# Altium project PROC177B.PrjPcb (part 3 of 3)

## Sheet PROC177B_CAN_LIN_PHY_Interface.SchDoc: CAN_LIN_PHY_INTERFACE
size 431 x 279 mm; Date: Not shown in title block; ApprovedBy: Not shown in title block; CheckedBy: Not shown in title block; Author: Not shown in title block; CompanyName: Not shown in title block; DrawnBy: Mistral; Engineer: Not shown in title block; Organization: Not shown in title block; Address1: Not shown in title block; Address2: Not shown in title block; Address3: Not shown in title block; Address4: Not shown in title block; DocumentNumber: 13; Revision: Use project parameter SCH_Rev; SheetNumber: 13; SheetTotal: 17; PageSetup: Record=PageOptions¦CenterHorizontal=True¦CenterVertical=True¦PrintScale=1.00¦XCorrection=1.00¦YCorrection=1.00¦PrintKind=0¦BorderSize=5000000¦LeftOffset=0¦BottomOffset=0¦Orientation=2¦PaperLength=1000¦PaperWidth=1000¦Scale=100¦PaperSource=15¦PrintQuality=600¦MediaType=1¦DitherType=10¦PaperKind=Letter¦PrintScaleMode=1
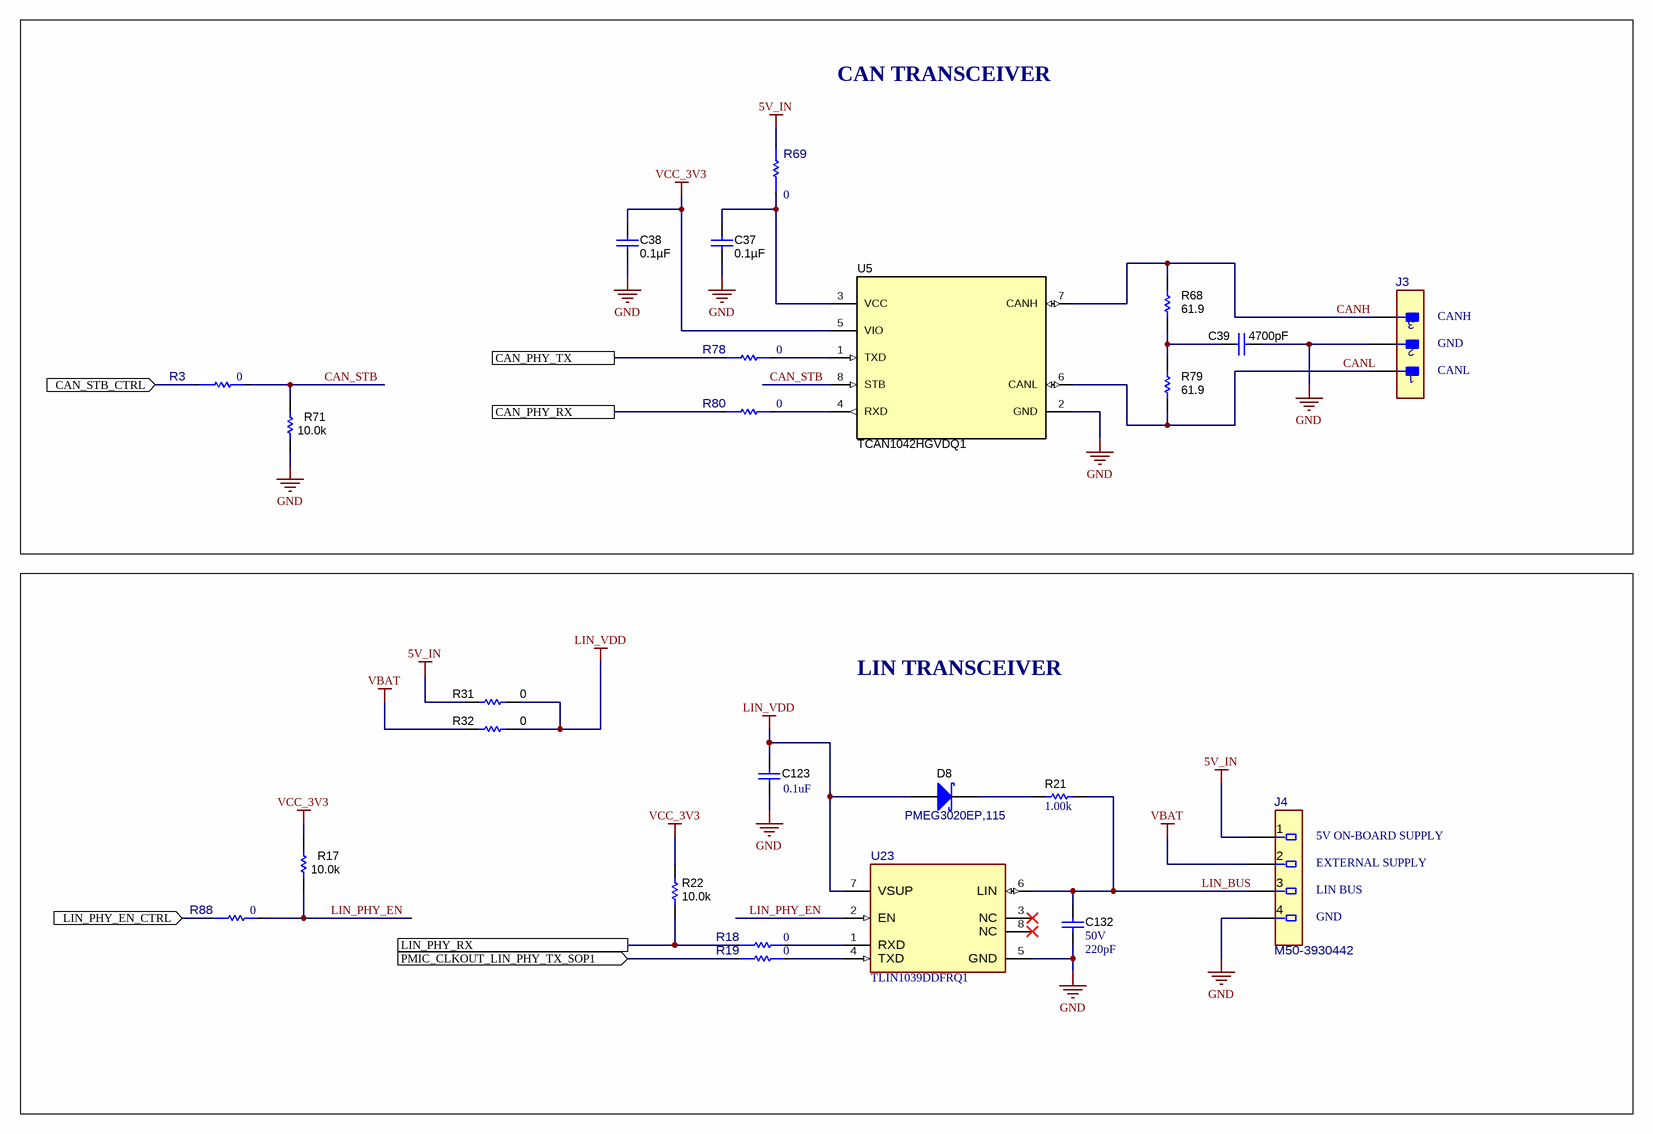
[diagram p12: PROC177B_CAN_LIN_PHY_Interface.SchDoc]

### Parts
C37  ValueDisplayed: 0.1µF  [0402]  (hidden comment: C0402C104K8RACTU)
C38  ValueDisplayed: 0.1µF  [0402]  (hidden comment: C0402C104K8RACTU)
C39  ValueDisplayed: 4700pF  [0402L]  (hidden comment: GCM155R71H472KA37D)
C123  ValueDisplayed: 0.1uF  [0402]  (hidden comment: GCM155R71H104KE02D)
C132  VDC_V: 50V  ValueDisplayed: 220pF  [0402]  (hidden comment: 885012005063)
D8  PMEG3020EP,115  [SOD-128]
J3  M50-3930342  [FP-M50-3930342_HDR3-MFG]  (value not drawn)
J4  M50-3930442  [FP-M50-3930442_HDR4-Recommended_Land_Pattern]
R3  value 0  [FP-ERJ-2GE0R00X_0402-MFG]  (hidden comment: ERJ-2GE0R00X)
R17  ValueDisplayed: 10.0k  [0402L]  (hidden comment: CRCW040210K0FKED)
R18  value 0  [FP-ERJ-2GE0R00X_0402-MFG]  (hidden comment: ERJ-2GE0R00X)
R19  value 0  [FP-ERJ-2GE0R00X_0402-MFG]  (hidden comment: ERJ-2GE0R00X)
R21  ValueDisplayed: 1.00k  [0402]  (hidden comment: CRCW04021K00FKED)
R22  ValueDisplayed: 10.0k  [0402L]  (hidden comment: CRCW040210K0FKED)
R31  ValueDisplayed: 0  [0603]  (hidden comment: MCT06030Z0000ZP500)
R32  ValueDisplayed: 0  [0603]  (hidden comment: MCT06030Z0000ZP500)
R68  ValueDisplayed: 61.9  [0402L]  (hidden comment: CRCW040261R9FKED)
R69  value 0  [FP-ERJ-2GE0R00X_0402-MFG]  (hidden comment: ERJ-2GE0R00X)
R71  ValueDisplayed: 10.0k  [0402L]  (hidden comment: CRCW040210K0FKED)
R78  value 0  [FP-ERJ-2GE0R00X_0402-MFG]  (hidden comment: ERJ-2GE0R00X)
R79  ValueDisplayed: 61.9  [0402L]  (hidden comment: CRCW040261R9FKED)
R80  value 0  [FP-ERJ-2GE0R00X_0402-MFG]  (hidden comment: ERJ-2GE0R00X)
R88  value 0  [FP-ERJ-2GE0R00X_0402-MFG]  (hidden comment: ERJ-2GE0R00X)
U5  TCAN1042HGVDQ1  [D0008A_L]
U23  TLIN1039DDFRQ1  [DDF0008A-MFG]

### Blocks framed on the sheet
CAN TRANSCEIVER: C37-C39 J3 R3 R68 R69 R71 R78-R80 U5
LIN TRANSCEIVER: C123 C132 D8 J4 R17-R19 R21 R22 R31 R32 R88 U23

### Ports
CAN_PHY_RX, CAN_PHY_TX, CAN_STB_CTRL (in), LIN_PHY_EN_CTRL (in), LIN_PHY_RX, PMIC_CLKOUT_LIN_PHY_TX_SOP1 (in)

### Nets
5V_IN: J4.1 R31.1 R69.2
GND: C37.1 C38.1 C39.1 C123.2 C132.2 J3.2 J4.4 R71.1 U5.2(GND) U23.5(GND)
LIN_VDD: C123.1 D8.2(A) R31.2 R32.2 U23.7(VSUP)
VBAT: J4.2 R32.1
VCC_3V3: C38.2 R17.2 R22.2 U5.5(VIO)
CAN_PHY_RX: R80.1 ; port CAN_PHY_RX
CAN_PHY_TX: R78.1 ; port CAN_PHY_TX
CAN_STB: R3.2 R71.2 U5.8(STB)
CAN_STB_CTRL: R3.1 ; port CAN_STB_CTRL
CANH: J3.3 R68.2 U5.7(CANH)
CANL: J3.1 R79.1 U5.6(CANL)
LIN_BUS: C132.1 J4.3 R21.1 U23.6(LIN)
LIN_PHY_EN: R17.1 R88.2 U23.2(EN)
LIN_PHY_EN_CTRL: R88.1 ; port LIN_PHY_EN_CTRL
LIN_PHY_RX: R18.1 R22.1 ; port LIN_PHY_RX
PMIC_CLKOUT_LIN_PHY_TX_SOP1: R19.1 ; port PMIC_CLKOUT_LIN_PHY_TX_SOP1
NetC37_2: C37.2 R69.1 U5.3(VCC)
NetC39_2: C39.2 R68.1 R79.2
NetD8_1: D8.1(K) R21.2
NetR18_2: R18.2 U23.1(RXD)
NetR19_2: R19.2 U23.4(TXD)
NetR78_2: R78.2 U5.1(TXD)
NetR80_2: R80.2 U5.4(RXD)

Not connected (* = marked no-connect by the designer): U23 3(NC)* 8(NC)*

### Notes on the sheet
- (near J3) CANH
- (near J3) GND
- (near J3) CANL
- (near J4) 5V ON-BOARD SUPPLY
- (near J4) EXTERNAL SUPPLY
- (near J4) LIN BUS
- (near J4) GND

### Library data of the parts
C37 C38 = CMP-0078241-1: CAP, CERM, 0.1 µF, 10 V,+/- 10%, X7R, 0402; Manufacturer: Kemet; TaMin_C: -55°C; Polarized: N; SizeAreaWB_mm2: 3; U/M: EA; Value: 0.1uF; TaMax_C: 125°C; SizeZ_mm: 0.6; SizeX_mm: 1; SizeY_mm: 0.5; Value2: 10V; CompType: Capacitor; Cap_F: 100nF; AEC Category: Q200
C39 = CMP-0006361-2: CAP, CERM, 4700 pF, 50 V, +/- 10%, X7R, AEC-Q200 Grade 1, 0402; Manufacturer: MuRata; TaMin_C: -55°C; Polarized: N; SizeAreaWB_mm2: 3; Value1: Unknown; U/M: EA; Value: 4700pF; TaMax_C: 125°C; SizeZ_mm: 0.6; SizeX_mm: 1; SizeY_mm: 0.5; Cap_Case: 0402; Value2: 50V; AEC Qualified: Y; Cap_F: 4.7nF; AEC Category: Q200
C123 = CMP-0006356-2: CAP, CERM, 0.1 uF, 50 V, +/- 10%, X7R, AEC-Q200 Grade 1, 0402; Manufacturer: MuRata; TaMin_C: -55°C; Polarized: N; SizeAreaWB_mm2: 3; Value1: Unknown; U/M: EA; Value: 0.1uF; TaMax_C: 125°C; SizeZ_mm: 0.6; SizeX_mm: 1; SizeY_mm: 0.5; Value2: 50V; AEC Qualified: Y; Cap_F: 100nF; AEC Category: Q200
C132 = CMP-0006218-2: CAP, CERM, 220 pF, 50 V, +/- 5%, C0G/NP0, 0402; Manufacturer: Wurth Elektronik; TaMin_C: -55°C; Polarized: N; SizeAreaWB_mm2: 3; Value1: Unknown; U/M: EA; Value: 220pF; TaMax_C: 125°C; SizeZ_mm: 0.6; SizeX_mm: 1; SizeY_mm: 0.5; AEC Category: Q200
D8 = CMP-0078758-2: Diode, Schottky, 30 V, 2 A, AEC-Q101, SOD-128; Manufacturer: Nexperia; Value2: 0.36V; SizeAreaWB_mm2: 19.6; Io_A: 2A; Value: 30V; AEC Qualified: Y; TJmax_C: 150°C; SizeX_mm: 4.6; AEC Category: Q101; SizeY_mm: 2.5; SizeArea_mm2: 11.5; Vf_V: 3.6dV; SizeZ_mm: 1.1
J3 = CMP-0087785-1: CONN HEADER R/A 3POS 1.27MM; Manufacturer: Harwin; Row_Count: 1; Current_A: 1A; ContactFinish: Gold,Nickel
J4 = CMP-0087187-1: CONN HDR 1.27MM R/A AU 4POS; Manufacturer: Harwin Inc.; ContactFinish: Gold; Current_A: 1A; Row_Count: 1
R3 R18 R19 R69 R78 R80 R88 = CMP-0002710-1: 0 Ohms Jumper Chip Resistor 0402 (1005 Metric) Automotive AEC-Q200 Thick Film; Manufacturer: Panasonic; SizeZ_mm: 0.4mm; AEC Qualified: Yes; AEC Grade: Grade 0; Power: 100mW
R17 R22 R71 = CMP-0025958-3: RES, 10.0 k, 1%, 0.063 W, AEC-Q200 Grade 0, 0402; Manufacturer: Vishay-Dale; Power_W: 63mW; TempCo: 100 ppm/C; Value_Code: 10k0; Value: 10.0k; EIA_Code: E96; Res_ohm: 10k; SizeX_mm: 1; SizeY_mm: 0.5; SizeZ_mm: 0.6; Value2: 0.063W; AEC Qualified: Y; VDC_V: 50V; AEC Category: Q200; AEC Grade: 0
R21 = CMP-0026071-3: RES, 1.00 k, 1%, 0.063 W, AEC-Q200 Grade 0, 0402; Manufacturer: Vishay-Dale; Power_W: 63mW; TempCo: 100 ppm/C; Value_Code: 1k00; Value: 1.00k; EIA_Code: E96; Res_ohm: 1k; SizeX_mm: 1; SizeY_mm: 0.5; SizeZ_mm: 0.6; Value2: 0.063W; AEC Qualified: Y; VDC_V: 50V; AEC Category: Q200; AEC Grade: 0
R31 R32 = CMP-0025884-3: RES, 0, 5%, 0.125 W, 0603; Manufacturer: Vishay/Beyschlag; Power_W: 125mW; TempCo: ppm/C; Value_Code: 0000; U/M: EA; Value: 0; EIA_Code: E24; SizeX_mm: 1.6; SizeY_mm: 0.8; SizeZ_mm: 1; Value2: 0.125W; SizeArea_mm2: 1.28; CompType: Resistor; AEC Qualified: N; AEC Category: Q200; INSTALATION: DNP
R68 R79 = CMP-0026491-2: RES, 61.9, 1%, 0.063 W, AEC-Q200 Grade 0, 0402; Manufacturer: Vishay-Dale; Power_W: 63mW; TempCo: 100 ppm/C; Value_Code: 61R9; Value: 61.9; EIA_Code: E96; SizeX_mm: 1; SizeY_mm: 0.5; SizeZ_mm: 0.6; Value2: 0.063W; AEC Qualified: Y; VDC_V: 50V; AEC Category: Q200; AEC Grade: 0
U5 = CMP-0075992-1: Automotive Fault Protected CAN Transceiver With Flexible Data-Rate, D0008A (SOIC-8); Manufacturer: Texas Instruments; Alternate PartNumber: TCAN1042HGVDRQ1; SizeAreaWB_mm2: 56.58; SizeArea_mm2: 30.38; SizeZ_mm: 1.75; SizeY_mm: 6.2; U/M: EA; CompType: IC; SizeX_mm: 4.9
U23 = CMP-0090433-1: Local Interconnect Network (LIN) Transceiver with Dominant State Timeout; Manufacturer: Texas Instruments; Max Supply Voltage: 36V; SizeZ_mm: 1.1mm; Min Supply Voltage: 4.5V; Standoff Height: 0mm; Nominal Supply Current: 0.3-1.2mA; AEC Grade: Grade 0; TJmax_C: +150°C; Interface: UART,LIN,SCI; AEC Qualified: Yes

## Sheet PROC177B_FTDI.SchDoc: FTDI_USB to SPI_Converter
size 431 x 279 mm; Date: Not shown in title block; ApprovedBy: Not shown in title block; CheckedBy: Not shown in title block; Author: Not shown in title block; CompanyName: Not shown in title block; DrawnBy: Mistral; Engineer: Not shown in title block; Organization: Not shown in title block; Address1: Not shown in title block; Address2: Not shown in title block; Address3: Not shown in title block; Address4: Not shown in title block; DocumentNumber: 14; Revision: Use project parameter SCH_Rev; SheetNumber: 14; SheetTotal: 17; PageSetup: Record=PageOptions¦CenterHorizontal=True¦CenterVertical=True¦PrintScale=1.00¦XCorrection=1.00¦YCorrection=1.00¦PrintKind=0¦BorderSize=5000000¦LeftOffset=0¦BottomOffset=0¦Orientation=2¦PaperLength=1000¦PaperWidth=1000¦Scale=100¦PaperSource=15¦PrintQuality=600¦MediaType=1¦DitherType=10¦PaperKind=Letter¦PrintScaleMode=1
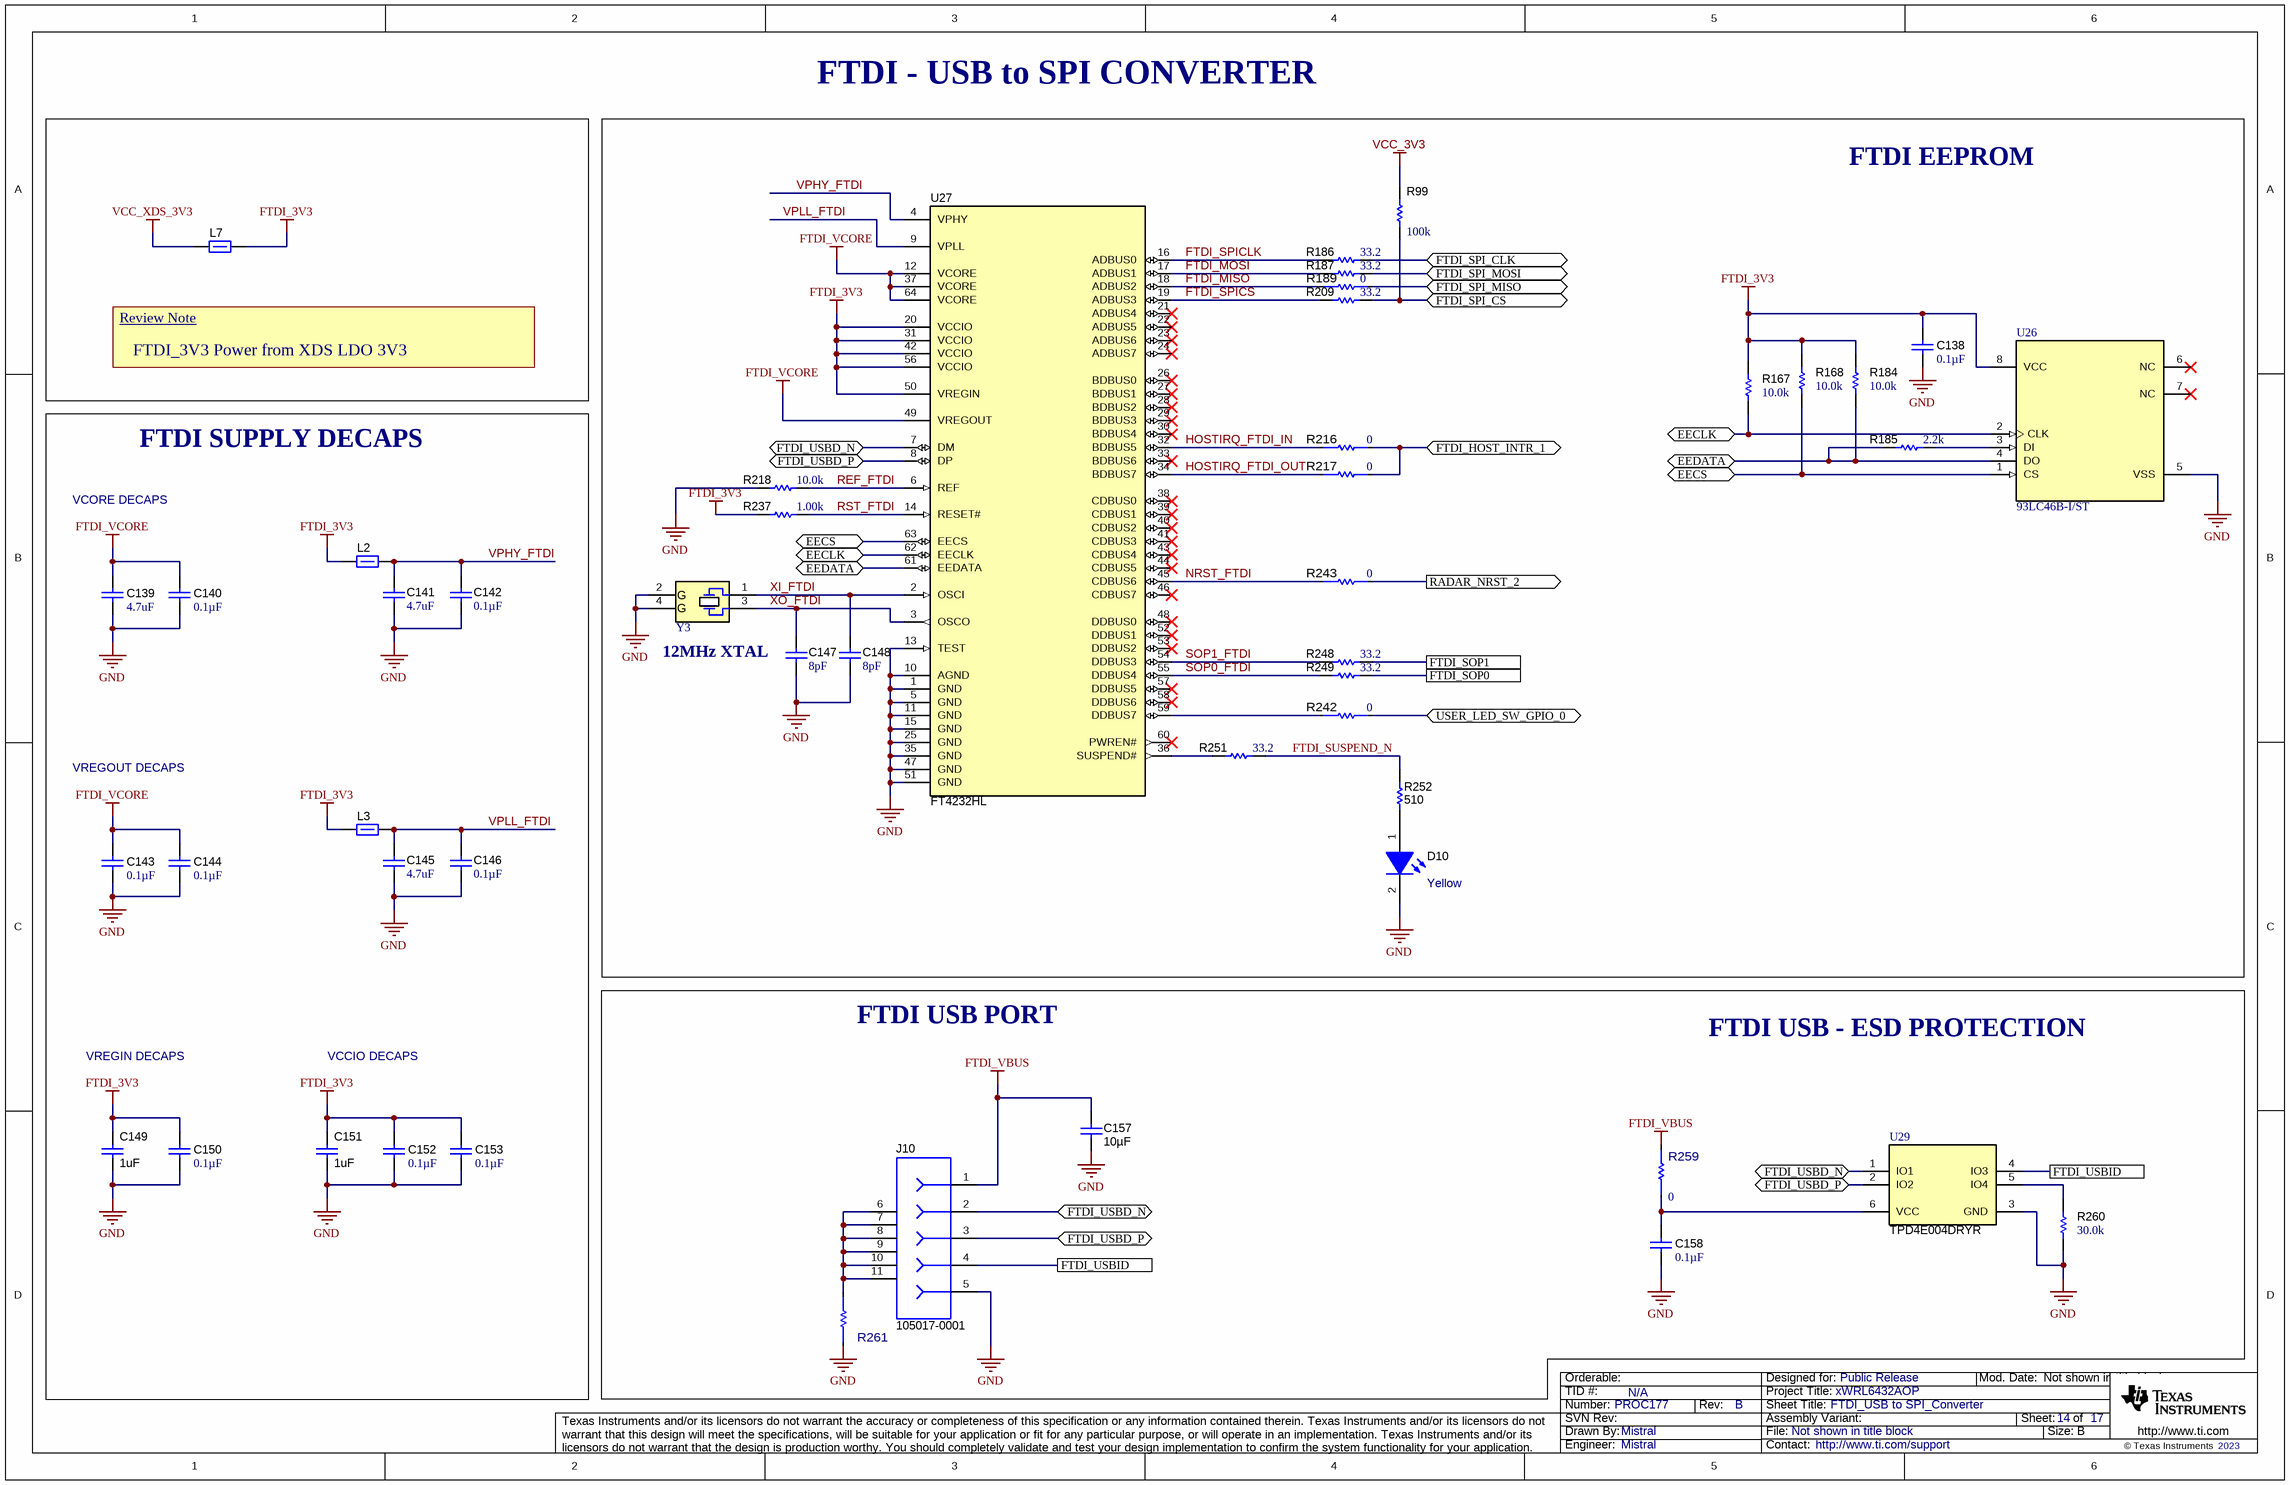
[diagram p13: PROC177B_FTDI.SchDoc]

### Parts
C138  ValueDisplayed: 0.1µF  [0402]  (hidden comment: C0402C104K8RACTU)
C139  ValueDisplayed: 4.7uF  [0603L]  (hidden comment: C1608X7S1A475K080AC)
C140  ValueDisplayed: 0.1µF  [0402]  (hidden comment: C0402C104K8RACTU)
C141  ValueDisplayed: 4.7uF  [0603L]  (hidden comment: C1608X7S1A475K080AC)
C142  ValueDisplayed: 0.1µF  [0402]  (hidden comment: C0402C104K8RACTU)
C143  ValueDisplayed: 0.1µF  [0402]  (hidden comment: C0402C104K8RACTU)
C144  ValueDisplayed: 0.1µF  [0402]  (hidden comment: C0402C104K8RACTU)
C145  ValueDisplayed: 4.7uF  [0603L]  (hidden comment: C1608X7S1A475K080AC)
C146  ValueDisplayed: 0.1µF  [0402]  (hidden comment: C0402C104K8RACTU)
C147  Cap_F: 8pF  [0402L]  (hidden comment: GCM1555C1H8R0DA16D)
C148  Cap_F: 8pF  [0402L]  (hidden comment: GCM1555C1H8R0DA16D)
C149  ValueDisplayed: 1uF  [0603]  (hidden comment: GCM188R71C105KA64D)
C150  ValueDisplayed: 0.1µF  [0402]  (hidden comment: C0402C104K8RACTU)
C151  ValueDisplayed: 1uF  [0603]  (hidden comment: GCM188R71C105KA64D)
C152  ValueDisplayed: 0.1µF  [0402]  (hidden comment: C0402C104K8RACTU)
C153  ValueDisplayed: 0.1µF  [0402]  (hidden comment: C0402C104K8RACTU)
C157  Cap_F: 10µF  [0805L]  (hidden comment: CL21B106KOQNNNE)
C158  ValueDisplayed: 0.1µF  [0402]  (hidden comment: C0402C104K8RACTU)
D10  value Yellow  [TLMx1000_Yellow]  (hidden comment: TLMY1000-GS08)
J10  105017-0001  [CONN_105017-0001]
L2  BLM15HG601SN1D  [0402L]  (value not drawn)
L3  BLM15HG601SN1D  [0402L]  (value not drawn)
L7  BLM15HG601SN1D  [0402L]  (value not drawn)
R99  ValueDisplayed: 100k  [0402]  (hidden comment: CRCW0402100KFKED)
R167  ValueDisplayed: 10.0k  [0402L]  (hidden comment: CRCW040210K0FKED)
R168  ValueDisplayed: 10.0k  [0402L]  (hidden comment: CRCW040210K0FKED)
R184  ValueDisplayed: 10.0k  [0402L]  (hidden comment: CRCW040210K0FKED)
R185  ValueDisplayed: 2.2k  [0402L]  (hidden comment: CRCW04022K20JNED)
R186  ValueDisplayed: 33.2  [0402]  (hidden comment: CRCW040233R2FKED)
R187  ValueDisplayed: 33.2  [0402]  (hidden comment: CRCW040233R2FKED)
R189  value 0  [FP-ERJ-2GE0R00X_0402-MFG]  (hidden comment: ERJ-2GE0R00X)
R209  ValueDisplayed: 33.2  [0402]  (hidden comment: CRCW040233R2FKED)
R216  value 0  [FP-ERJ-2GE0R00X_0402-MFG]  (hidden comment: ERJ-2GE0R00X)
R217  value 0  [FP-ERJ-2GE0R00X_0402-MFG]  (hidden comment: ERJ-2GE0R00X)
R218  ValueDisplayed: 10.0k  [0402L]  (hidden comment: CRCW040210K0FKED)
R237  ValueDisplayed: 1.00k  [0402]  (hidden comment: CRCW04021K00FKED)
R242  value 0  [FP-ERJ-2GE0R00X_0402-MFG]  (hidden comment: ERJ-2GE0R00X)
R243  value 0  [FP-ERJ-2GE0R00X_0402-MFG]  (hidden comment: ERJ-2GE0R00X)
R248  ValueDisplayed: 33.2  [0402]  (hidden comment: CRCW040233R2FKED)
R249  ValueDisplayed: 33.2  [0402]  (hidden comment: CRCW040233R2FKED)
R251  ValueDisplayed: 33.2  [0402]  (hidden comment: CRCW040233R2FKED)
R252  ValueDisplayed: 510  [0402L]  (hidden comment: ERJ-2GEJ511X)
R259  value 0  [FP-ERJ-2GE0R00X_0402-MFG]  (hidden comment: ERJ-2GE0R00X)
R260  ValueDisplayed: 30.0k  [0402L]  (hidden comment: CRCW040230K0FKED)
R261  ERJ-2GE0R00X  [FP-ERJ-2GE0R00X_0402-MFG]  (value not drawn)
U26  93LC46B-I/ST  [TSSOP-8]
U27  FT4232HL  [LQFP64_N]
U29  TPD4E004DRYR  [DRY0006A]
Y3  NX3225SA-12.000M-STD-CRS-2  [NDK_NX3225SA]  (value not drawn)

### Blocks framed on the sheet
FTDI_3V3 Power from XDS LDO 3V3: L7
FTDI EEPROM: C138 C147 C148 D10 R99 R167 R168 R184-R187 R189 R209 R216-R218 R237 R242 R243 R248 R249 R251 R252 U26 U27 Y3
FTDI SUPPLY DECAPS: C139-C146 C149-C153 L2 L3

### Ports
EECLK (bidir), EECS (bidir), EEDATA (bidir), FTDI_HOST_INTR_1 (bidir), FTDI_SOP0, FTDI_SOP1, FTDI_SPI_CLK (bidir), FTDI_SPI_CS (bidir), FTDI_SPI_MISO (bidir), FTDI_SPI_MOSI (bidir), FTDI_USBD_N (bidir), FTDI_USBD_P (bidir), FTDI_USBID, RADAR_NRST_2 (out), USER_LED_SW_GPIO_0 (bidir)

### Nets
FTDI_3V3: C138.1 C149.2 C150.1 C151.2 C152.1 C153.1 L2.1 L3.1 L7.2 R167.2 R168.2 R184.2 R237.1 U26.8(VCC) U27.20(VCCIO) U27.31(VCCIO) U27.42(VCCIO) U27.50(VREGIN) U27.56(VCCIO)
FTDI_VBUS: C157.1 J10.1 R259.2
FTDI_VCORE: C139.1 C140.1 C143.1 C144.1 U27.12(VCORE) U27.37(VCORE) U27.49(VREGOUT) U27.64(VCORE)
GND: C138.2 C139.2 C140.2 C141.2 C142.1 C143.2 C144.2 C145.2 C146.1 C147.2 C148.2 C149.1 C150.2 C151.1 C152.2 C153.2 C157.2 C158.2 D10.2(K) J10.5 R218.1 R260.1 R261.1 U26.5(VSS) U27.1(GND) U27.5(GND) U27.10(AGND) U27.11(GND) U27.13(TEST) U27.15(GND) U27.25(GND) U27.35(GND) U27.47(GND) U27.51(GND) U29.3(GND) Y3.2(GND) Y3.4(GND)
VCC_3V3: R99.2
VCC_XDS_3V3: L7.1
EECLK: R167.1 U26.2(CLK) U27.62(EECLK) ; port EECLK
EECS: R168.1 U26.1(CS) U27.63(EECS) ; port EECS
EEDATA: R184.1 R185.1 U26.4(DO) U27.61(EEDATA) ; port EEDATA
FTDI_HOST_INTR_1: R216.2 R217.2 ; port FTDI_HOST_INTR_1
FTDI_MISO: R189.1 U27.18(ADBUS2)
FTDI_MOSI: R187.1 U27.17(ADBUS1)
FTDI_SOP0: R249.2 ; port FTDI_SOP0
FTDI_SOP1: R248.2 ; port FTDI_SOP1
FTDI_SPI_CLK: R186.2 ; port FTDI_SPI_CLK
FTDI_SPI_CS: R99.1 R209.2 ; port FTDI_SPI_CS
FTDI_SPI_MISO: R189.2 ; port FTDI_SPI_MISO
FTDI_SPI_MOSI: R187.2 ; port FTDI_SPI_MOSI
FTDI_SPICLK: R186.1 U27.16(ADBUS0)
FTDI_SPICS: R209.1 U27.19(ADBUS3)
FTDI_SUSPEND_N: R251.2 R252.1
FTDI_USBD_N: J10.2 U27.7(DM) U29.1(IO1) ; port FTDI_USBD_N
FTDI_USBD_P: J10.3 U27.8(DP) U29.2(IO2) ; port FTDI_USBD_P
FTDI_USBID: J10.4 U29.4(IO3) ; port FTDI_USBID
HOSTIRQ_FTDI_IN: R216.1 U27.32(BDBUS5)
HOSTIRQ_FTDI_OUT: R217.1 U27.34(BDBUS7)
NRST_FTDI: R243.1 U27.45(CDBUS6)
RADAR_NRST_2: R243.2 ; port RADAR_NRST_2
REF_FTDI: R218.2 U27.6(REF)
RST_FTDI: R237.2 U27.14(RESET#)
SOP0_FTDI: R249.1 U27.55(DDBUS4)
SOP1_FTDI: R248.1 U27.54(DDBUS3)
USER_LED_SW_GPIO_0: R242.2 ; port USER_LED_SW_GPIO_0
VPHY_FTDI: C141.1 C142.2 L2.2 U27.4(VPHY)
VPLL_FTDI: C145.1 C146.2 L3.2 U27.9(VPLL)
XI_FTDI: C148.1 U27.2(OSCI) Y3.1
XO_FTDI: C147.1 U27.3(OSCO) Y3.3
NetC158_1: C158.1 R259.1 U29.6(VCC)
NetD10_1: D10.1(A) R252.2
NetJ10_6: J10.6 J10.7 J10.8 J10.9 J10.10 J10.11 R261.2
NetR185_2: R185.2 U26.3(DI)
NetR242_1: R242.1 U27.59(DDBUS7)
NetR251_1: R251.1 U27.36(SUSPEND#)
NetR260_2: R260.2 U29.5(IO4)

Not connected (* = marked no-connect by the designer): U26 6(NC)* 7(NC)*; U27 21(ADBUS4)* 22(ADBUS5)* 23(ADBUS6)* 24(ADBUS7)* 26(BDBUS0)* 27(BDBUS1)* 28(BDBUS2)* 29(BDBUS3)* 30(BDBUS4)* 33(BDBUS6)* 38(CDBUS0)* 39(CDBUS1)* 40(CDBUS2)* 41(CDBUS3)* 43(CDBUS4)* 44(CDBUS5)* 46(CDBUS7)* 48(DDBUS0)* 52(DDBUS1)* 53(DDBUS2)* 57(DDBUS5)* 58(DDBUS6)* 60(PWREN#)*

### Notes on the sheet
- FTDI - USB to SPI CONVERTER
- Review Note
- VCORE DECAPS
- 12MHz XTAL
- VREGOUT DECAPS
- FTDI USB PORT
- VREGIN DECAPS
- VCCIO DECAPS
- FTDI USB - ESD PROTECTION

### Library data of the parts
C138 C140 C142-C144 C146 C150 C152 C153 = CMP-0078241-1: as C37 on sheet PROC177B_CAN_LIN_PHY_Interface
C139 C141 C145 = CMP-0007058-4: CAP, CERM, 4.7 uF, 10 V, +/- 10%, X7S, 0603; Manufacturer: TDK; TaMin_C: -55°C; Polarized: N; SizeAreaWB_mm2: 4.68; Value1: Unknown; U/M: EA; Value: 4.7uF; TaMax_C: 125°C; SizeZ_mm: 1; SizeX_mm: 1.6; SizeY_mm: 0.8; Cap_Case: 0603; Value2: 10V; SizeArea_mm2: 1.28; CompType: Capacitor; Cap_F: 4.7µF; AEC Category: Q200
C147 C148 = CMP-0087060-3: Cap Ceramic 8pF 50V C0G 0.5pF SMD 0402 125C Paper T/R; Manufacturer: Murata Electronics North America; AEC Qualified: Yes; TempCo: 30ppm/°C; AEC Grade: Grade 1; SizeZ_mm: 0.55mm
C149 C151 = CMP-0007136-5: CAP, CERM, 1 uF, 16 V, +/- 10%, X7R, AEC-Q200 Grade 1, 0603; Manufacturer: MuRata; TaMin_C: -55°C; Polarized: N; SizeAreaWB_mm2: 4.68; Value1: Unknown; U/M: EA; Value: 1uF; TaMax_C: 125°C; SizeZ_mm: 1; SizeX_mm: 1.6; SizeY_mm: 0.8; Value2: 16V; SizeArea_mm2: 1.28; CompType: Capacitor; AEC Qualified: Y; Cap_F: 1µF; AEC Category: Q200
C157 = CMP-0007995-2: CAP, CERM, 10 uF, 16 V, +/- 10%, X7R, 0805; Manufacturer: Samsung Electro-Mechanics; TaMin_C: -55°C; Polarized: N; SizeAreaWB_mm2: 6.75; Value1: Unknown; U/M: EA; Value: 10uF; TaMax_C: 125°C; SizeZ_mm: 1.45; SizeX_mm: 2; SizeY_mm: 1.25; Cap_Case: 0805; Value2: 16V; SizeArea_mm2: 2.5; AEC Category: Q200
C158 = CMP-0078241-1: CAP, CERM, 0.1 µF, 10 V,+/- 10%, X7R, 0402; Manufacturer: Kemet; TaMin_C: -55°C; Polarized: N; SizeAreaWB_mm2: 3; U/M: EA; Value: 0.1uF; TaMax_C: 125°C; SizeZ_mm: 0.6; SizeX_mm: 1; SizeY_mm: 0.5; Value2: 10V; Cap_F: 100nF; AEC Category: Q200
D10 = CMP-0078196-2: LED, Yellow, SMD; Manufacturer: Vishay-Semiconductor; Tjmax_C: 120°C; SizeAreaWB_mm2: 4.68; Vr_V: 6V; Power_TotalModule: 40mW; Angle: 160; SizeArea_mm2: 1.28; Ir_A: 10µA; SizeZ_mm: 0.65; Io_A: 2mA; Vf_V: 1.8V; SizeY_mm: 0.8; Value1: .04W; SizeX_mm: 1.6; Type: AlInGaP
J10 = CMP-0055293-1: Connector, Receptacle, Micro-USB Type B, R/A, Bottom Mount SMT; Manufacturer: Molex; CNHeader: FALSE; Green_Lifecycle: Active; Gender: Female; Green_REACh: Passed; CompType: USB; CT: TRUE
L2 L3 L7 = CMP-0081523-1: Ferrite Bead, 600 ohm @ 100 MHz, 0.3 A, 0402; Manufacturer: MuRata; SizeAreaWB_mm2: 3; SizeArea_mm2: 0.5; Value: 600 ohm; SizeZ_mm: 0.6; Imax_A: 3dA; ZTyp@100MHz_Ohm: 600; Value2: 0.3A; Value1: 0.7 ohm; DCR_ohm: 7d; SizeX_mm: 1; Ztyp@1GHz_Ohm: 1k
R99 = CMP-0025950-3: RES, 100 k, 1%, 0.063 W, AEC-Q200 Grade 0, 0402; Manufacturer: Vishay-Dale; Power_W: 63mW; TempCo: 100 ppm/C; Value: 100k; EIA_Code: E96; SizeX_mm: 1; SizeY_mm: 0.5; SizeZ_mm: 0.6; Value2: 0.063W; AEC Qualified: Y; VDC_V: 50V; AEC Category: Q200; AEC Grade: 0
R167 R168 R184 R218 = CMP-0025958-3: as R17 on sheet PROC177B_CAN_LIN_PHY_Interface
R185 = CMP-0026890-5: RES, 2.2 k, 5%, 0.063 W, AEC-Q200 Grade 0, 0402; Manufacturer: Vishay-Dale; Power_W: 63mW; TempCo: 200 ppm/C; Value_Code: 2k20; Value: 2.2k; EIA_Code: E24; SizeX_mm: 1; SizeY_mm: 0.5; SizeZ_mm: 0.6; Value2: 0.063W; AEC Qualified: Y; VDC_V: 50V; AEC Category: Q200; AEC Grade: 0
R186 R187 R209 R248 R249 R251 = CMP-0026299-2: RES, 33.2, 1%, 0.063 W, AEC-Q200 Grade 0, 0402; Manufacturer: Vishay-Dale; Power_W: 63mW; TempCo: 100 ppm/C; Value_Code: 33R2; Value: 33.2; EIA_Code: E96; SizeX_mm: 1; SizeY_mm: 0.5; SizeZ_mm: 0.6; Value2: 0.063W; AEC Qualified: Y; VDC_V: 50V; AEC Category: Q200; AEC Grade: 0
R189 R216 R217 R242 R243 R259 = CMP-0002710-1: as R3 on sheet PROC177B_CAN_LIN_PHY_Interface
R237 = CMP-0026071-3: as R21 on sheet PROC177B_CAN_LIN_PHY_Interface
R252 = CMP-0078212-1: RES, 510, 5%, 0.1 W, AEC-Q200 Grade 0, 0402; Manufacturer: Panasonic; Value_Code: 510R; SizeArea_mm2: 0.5; AEC Qualified: Y; AEC Category: Q200; Value: 510; SizeZ_mm: 0.6; EIA_Code: E24; TempCo: 200 ppm/C; AEC Grade: 0; Power_W: 100mW; VDC_V: 50V; Value2: 0.1W; U/M: EA; SizeX_mm: 1
R260 = CMP-0078244-2: RES, 30.0 k, 1%, 0.063 W, AEC-Q200 Grade 0, 0402; Manufacturer: Vishay-Dale; Power_W: 63mW; Green_Lifecycle: Active; TempCo: 100 ppm/C; Value_Code: 30k0; Green_REACh: Passed; Value: 30.0k; Res_ohm: 30k; SizeX_mm: 1; SizeY_mm: 0.5; SizeZ_mm: 0.6; Value2: 0.063W; AEC Qualified: Y; VDC_V: 50V; AEC Grade: 0; AEC Category: Q200
R261 = CMP-0002710-1: 0 Ohms Jumper Chip Resistor 0402 (1005 Metric) Automotive AEC-Q200 Thick Film; Manufacturer: Panasonic; Value: 0; SizeZ_mm: 0.4mm; AEC Qualified: Yes; AEC Grade: Grade 0; Power: 100mW
U26 = CMP-0081524-1: 1K Microwire Compatible Serial EEPROM, TSSOP-8; Manufacturer: Microchip; SizeArea_mm2: 19.2; SizeAreaWB_mm2: 42; SizeY_mm: 3; SizeZ_mm: 1.2; SizeX_mm: 6.4
U27 = CMP-0004747-1: Quad High Speed USB to Multipurpose UART/MPSSE IC; Manufacturer: FTDI
U29 = CMP-0043115-3: 4-Channel ESD Protection Array for High-Speed Data Interfaces, DRY0006A (USON-6); Manufacturer: Texas Instruments; IO Leakage Current(nA): 1; USB High Speed: TRUE; IO Capacitance(Typ)(pF): 1.6; Eco-Plan: Green (RoHS & no Sb/Br); IEC 61000-4-2 Contact(+/- kV): 8; Breakdown Voltage(Min)(V): 6; IEC 61000-4-2 Air-Gap(+/- kV): 12; AEC Category: Q200; AEC Qualified: N; CompType: IC; SizeAreaWB_mm2: 4.9; SizeArea_mm2: 1.45; SizeX_mm: 1.0; SizeZ_mm: 0.6; Rating: Catalog
Y3 = CMP-0081529-1: Crystal, 12 MHz, 15 ppm, 8 pF, AEC-Q200 Grade 1, SMD; Manufacturer: NDK; TaMin_C: -40°C; Frequency Tolerance: 15 ppm; Frequency Stability: 50 ppm; Load Capacitance: 8 pF; Frequency_Fixed: 12MHz; TaMax_C: 125°C; AEC Qualified: Y; AEC Grade: 1; AEC Category: Q200

## Sheet PROC177B_DCA1000_Connector_Reset.SchDoc: DCA1000_CONN_RESET
size 431 x 279 mm; Date: Not shown in title block; ApprovedBy: Not shown in title block; CheckedBy: Not shown in title block; Author: Not shown in title block; CompanyName: Not shown in title block; DrawnBy: Mistral; Engineer: Not shown in title block; Organization: Not shown in title block; Address1: Not shown in title block; Address2: Not shown in title block; Address3: Not shown in title block; Address4: Not shown in title block; DocumentNumber: 15; Revision: Use project parameter SCH_Rev; SheetNumber: 15; SheetTotal: 17; PageSetup: Record=PageOptions¦CenterHorizontal=True¦CenterVertical=True¦PrintScale=1.00¦XCorrection=1.00¦YCorrection=1.00¦PrintKind=0¦BorderSize=5000000¦LeftOffset=0¦BottomOffset=0¦Orientation=2¦PaperLength=1000¦PaperWidth=1000¦Scale=100¦PaperSource=15¦PrintQuality=600¦MediaType=1¦DitherType=10¦PaperKind=Letter¦PrintScaleMode=1
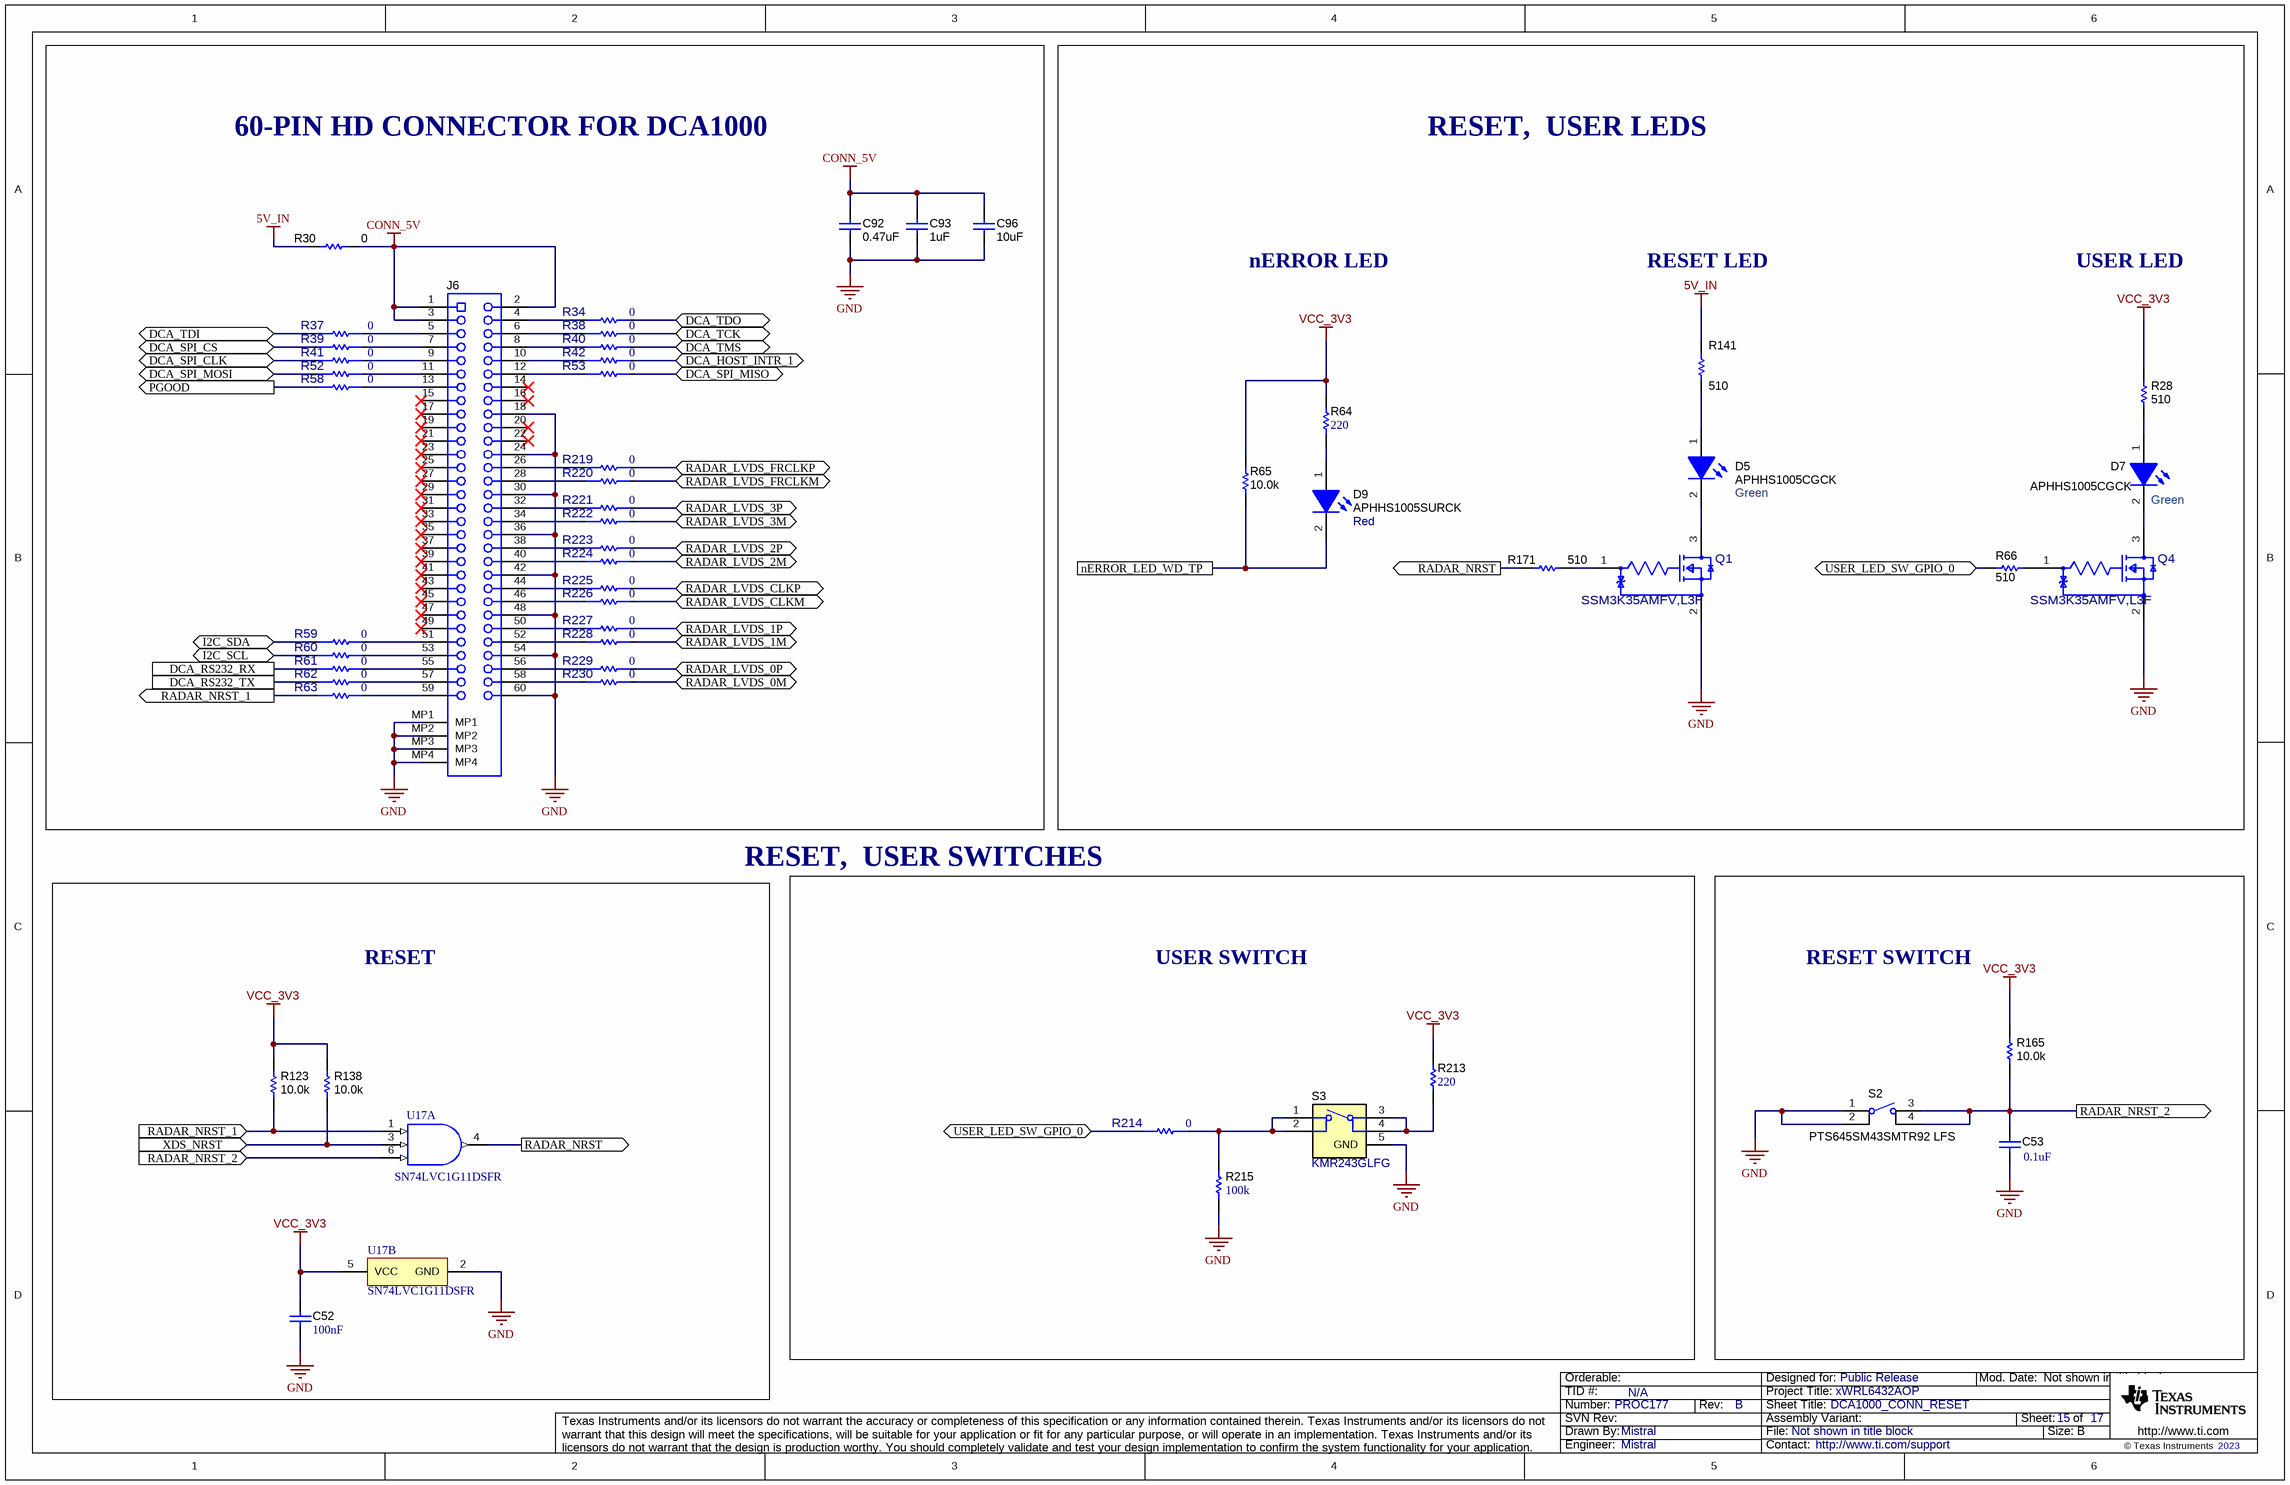
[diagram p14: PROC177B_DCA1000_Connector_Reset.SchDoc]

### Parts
C52  Cap_F: 100nF  [0402]  (hidden comment: GCM155R71H104KE02D)
C53  ValueDisplayed: 0.1uF  [0402]  (hidden comment: GCM155R71H104KE02D)
C92  ValueDisplayed: 0.47uF  [0402L]  (hidden comment: GCM155C71A474KE36D)
C93  ValueDisplayed: 1uF  [0402L]  (hidden comment: GRT155C81A105KE01D)
C96  ValueDisplayed: 10uF  [0603S]  (hidden comment: GRT188R61A106KE13D)
D5  APHHS1005CGCK  Color: Green  [APHHS1005_Green]
D7  APHHS1005CGCK  Color: Green  [APHHS1005_Green]
D9  APHHS1005SURCK  value Red  [APHHS1005_Red]
J6  QSH-030-01-L-D-A  [Samtec_QSH-030-01-X-D-A]  (value not drawn)
Q1  SSM3K35AMFV,L3F  [FP-SSM3K35AMFV,L3F_SOT-723-MFG]
Q4  SSM3K35AMFV,L3F  [FP-SSM3K35AMFV,L3F_SOT-723-MFG]
R28  ValueDisplayed: 510  [0402L]  (hidden comment: ERJ-2GEJ511X)
R30  ValueDisplayed: 0  [0603]  (hidden comment: MCT06030Z0000ZP500)
R34  value 0  [FP-ERJ-2GE0R00X_0402-MFG]  (hidden comment: ERJ-2GE0R00X)
R37  value 0  [FP-ERJ-2GE0R00X_0402-MFG]  (hidden comment: ERJ-2GE0R00X)
R38  value 0  [FP-ERJ-2GE0R00X_0402-MFG]  (hidden comment: ERJ-2GE0R00X)
R39  value 0  [FP-ERJ-2GE0R00X_0402-MFG]  (hidden comment: ERJ-2GE0R00X)
R40  value 0  [FP-ERJ-2GE0R00X_0402-MFG]  (hidden comment: ERJ-2GE0R00X)
R41  value 0  [FP-ERJ-2GE0R00X_0402-MFG]  (hidden comment: ERJ-2GE0R00X)
R42  value 0  [FP-ERJ-2GE0R00X_0402-MFG]  (hidden comment: ERJ-2GE0R00X)
R52  value 0  [FP-ERJ-2GE0R00X_0402-MFG]  (hidden comment: ERJ-2GE0R00X)
R53  value 0  [FP-ERJ-2GE0R00X_0402-MFG]  (hidden comment: ERJ-2GE0R00X)
R58  value 0  [FP-ERJ-2GE0R00X_0402-MFG]  (hidden comment: ERJ-2GE0R00X)
R59  value 0  [FP-ERJ-2GE0R00X_0402-MFG]  (hidden comment: ERJ-2GE0R00X)
R60  value 0  [FP-ERJ-2GE0R00X_0402-MFG]  (hidden comment: ERJ-2GE0R00X)
R61  value 0  [FP-ERJ-2GE0R00X_0402-MFG]  (hidden comment: ERJ-2GE0R00X)
R62  value 0  [FP-ERJ-2GE0R00X_0402-MFG]  (hidden comment: ERJ-2GE0R00X)
R63  value 0  [FP-ERJ-2GE0R00X_0402-MFG]  (hidden comment: ERJ-2GE0R00X)
R64  ValueDisplayed: 220  [0402]  (hidden comment: CRCW0402220RJNED)
R65  ValueDisplayed: 10.0k  [0402L]  (hidden comment: CRCW040210K0FKED)
R66  ValueDisplayed: 510  [0402L]  (hidden comment: ERJ-2GEJ511X)
R123  ValueDisplayed: 10.0k  [0402L]  (hidden comment: CRCW040210K0FKED)
R138  ValueDisplayed: 10.0k  [0402L]  (hidden comment: CRCW040210K0FKED)
R141  ValueDisplayed: 510  [0402L]  (hidden comment: ERJ-2GEJ511X)
R165  ValueDisplayed: 10.0k  [0402L]  (hidden comment: CRCW040210K0FKED)
R171  ValueDisplayed: 510  [0402L]  (hidden comment: ERJ-2GEJ511X)
R213  ValueDisplayed: 220  [0402]  (hidden comment: CRCW0402220RJNED)
R214  Res_ohm: 0  [FP-ERJ-2GE0R00X_0402-MFG]  (hidden comment: ERJ-2GE0R00X)
R215  value 100k  [0402]  (hidden comment: CRCW0402100KFKED)
R219  value 0  [FP-ERJ-2GE0R00X_0402-MFG]  (hidden comment: ERJ-2GE0R00X)
R220  value 0  [FP-ERJ-2GE0R00X_0402-MFG]  (hidden comment: ERJ-2GE0R00X)
R221  value 0  [FP-ERJ-2GE0R00X_0402-MFG]  (hidden comment: ERJ-2GE0R00X)
R222  value 0  [FP-ERJ-2GE0R00X_0402-MFG]  (hidden comment: ERJ-2GE0R00X)
R223  value 0  [FP-ERJ-2GE0R00X_0402-MFG]  (hidden comment: ERJ-2GE0R00X)
R224  value 0  [FP-ERJ-2GE0R00X_0402-MFG]  (hidden comment: ERJ-2GE0R00X)
R225  value 0  [FP-ERJ-2GE0R00X_0402-MFG]  (hidden comment: ERJ-2GE0R00X)
R226  value 0  [FP-ERJ-2GE0R00X_0402-MFG]  (hidden comment: ERJ-2GE0R00X)
R227  value 0  [FP-ERJ-2GE0R00X_0402-MFG]  (hidden comment: ERJ-2GE0R00X)
R228  value 0  [FP-ERJ-2GE0R00X_0402-MFG]  (hidden comment: ERJ-2GE0R00X)
R229  value 0  [FP-ERJ-2GE0R00X_0402-MFG]  (hidden comment: ERJ-2GE0R00X)
R230  value 0  [FP-ERJ-2GE0R00X_0402-MFG]  (hidden comment: ERJ-2GE0R00X)
S2  PTS645SM43SMTR92 LFS  [SW_PTS645SM43SMT]
S3  KMR243GLFG  [SW_KMR243GLFG]
U17  SN74LVC1G11DSFR  [DSF0006A]  (parts A,B of 2)

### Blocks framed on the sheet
60-PIN HD CONNECTOR FOR DCA1000: C92 C93 C96 J6 R30 R34 R37-R42 R52 R53 R58-R63 R219-R230
RESET,  USER LEDS: D5 D7 D9 Q1 Q4 R28 R64-R66 R141 R171
RESET: C52 R123 R138 U17
USER SWITCH: R213-R215 S3
RESET SWITCH: C53 R165 S2

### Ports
DCA_HOST_INTR_1 (bidir), DCA_RS232_RX, DCA_RS232_TX, DCA_SPI_CLK (bidir), DCA_SPI_CS (bidir), DCA_SPI_MISO (bidir), DCA_SPI_MOSI (bidir), DCA_TCK (bidir), DCA_TDI (bidir), DCA_TDO (bidir), DCA_TMS (bidir), I2C_SCL (bidir), I2C_SDA (bidir), nERROR_LED_WD_TP, PGOOD (out), RADAR_LVDS_0M (bidir), RADAR_LVDS_0P (bidir), RADAR_LVDS_1M (bidir), RADAR_LVDS_1P (bidir), RADAR_LVDS_2M (bidir), RADAR_LVDS_2P (bidir), RADAR_LVDS_3M (bidir), RADAR_LVDS_3P (bidir), RADAR_LVDS_CLKM (bidir), RADAR_LVDS_CLKP (bidir), RADAR_LVDS_FRCLKM (bidir), RADAR_LVDS_FRCLKP (bidir), RADAR_NRST (out), RADAR_NRST_1 (in), RADAR_NRST_1 (out), RADAR_NRST_2 (in), RADAR_NRST_2 (out), USER_LED_SW_GPIO_0 (bidir), XDS_NRST (in)

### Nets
5V_IN: R30.1 R141.2
CONN_5V: C92.1 C93.1 C96.2 J6.1 J6.2 J6.3 R30.2
GND: C52.1 C53.2 C92.2 C93.2 C96.1 J6.18 J6.24 J6.30 J6.36 J6.42 J6.48 J6.54 J6.60 J6.MP1 J6.MP2 J6.MP3 J6.MP4 Q1.2(S) Q4.2(S) R215.2 S2.1 S2.2 S3.5(GND) U17.2(GND)
VCC_3V3: C52.2 R28.2 R64.2 R65.1 R123.2 R138.2 R165.2 R213.2 U17.5(VCC)
DCA_HOST_INTR_1: R42.2 ; port DCA_HOST_INTR_1
DCA_RS232_RX: R61.1 ; port DCA_RS232_RX
DCA_RS232_TX: R62.1 ; port DCA_RS232_TX
DCA_SPI_CLK: R41.1 ; port DCA_SPI_CLK
DCA_SPI_CS: R39.1 ; port DCA_SPI_CS
DCA_SPI_MISO: R53.2 ; port DCA_SPI_MISO
DCA_SPI_MOSI: R52.1 ; port DCA_SPI_MOSI
DCA_TCK: R38.2 ; port DCA_TCK
DCA_TDI: R37.1 ; port DCA_TDI
DCA_TDO: R34.2 ; port DCA_TDO
DCA_TMS: R40.2 ; port DCA_TMS
I2C_SCL: R60.1 ; port I2C_SCL
I2C_SDA: R59.1 ; port I2C_SDA
nERROR_LED_WD_TP: D9.2(K) R65.2 ; port nERROR_LED_WD_TP
PGOOD: R58.1 ; port PGOOD
RADAR_LVDS_0M: R230.2 ; port RADAR_LVDS_0M
RADAR_LVDS_0P: R229.2 ; port RADAR_LVDS_0P
RADAR_LVDS_1M: R228.2 ; port RADAR_LVDS_1M
RADAR_LVDS_1P: R227.2 ; port RADAR_LVDS_1P
RADAR_LVDS_2M: R224.2 ; port RADAR_LVDS_2M
RADAR_LVDS_2P: R223.2 ; port RADAR_LVDS_2P
RADAR_LVDS_3M: R222.2 ; port RADAR_LVDS_3M
RADAR_LVDS_3P: R221.2 ; port RADAR_LVDS_3P
RADAR_LVDS_CLKM: R226.2 ; port RADAR_LVDS_CLKM
RADAR_LVDS_CLKP: R225.2 ; port RADAR_LVDS_CLKP
RADAR_LVDS_FRCLKM: R220.2 ; port RADAR_LVDS_FRCLKM
RADAR_LVDS_FRCLKP: R219.2 ; port RADAR_LVDS_FRCLKP
RADAR_NRST: R171.2 U17.4(Y) ; port RADAR_NRST
RADAR_NRST_1: R63.1 R123.1 U17.1(A) ; port RADAR_NRST_1
RADAR_NRST_2: C53.1 R165.1 S2.3 S2.4 U17.6(C) ; port RADAR_NRST_2
USER_LED_SW_GPIO_0: R66.2 R214.2 ; port USER_LED_SW_GPIO_0
XDS_NRST: R138.1 U17.3(B) ; port XDS_NRST
NetD5_1: D5.1(A) R141.1
NetD5_2: D5.2(K) Q1.3(D)
NetD7_1: D7.1(A) R28.1
NetD7_2: D7.2(K) Q4.3(D)
NetD9_1: D9.1(A) R64.1
NetJ6_4: J6.4 R34.1
NetJ6_5: J6.5 R37.2
NetJ6_6: J6.6 R38.1
NetJ6_7: J6.7 R39.2
NetJ6_8: J6.8 R40.1
NetJ6_9: J6.9 R41.2
NetJ6_10: J6.10 R42.1
NetJ6_11: J6.11 R52.2
NetJ6_12: J6.12 R53.1
NetJ6_13: J6.13 R58.2
NetJ6_26: J6.26 R219.1
NetJ6_28: J6.28 R220.1
NetJ6_32: J6.32 R221.1
NetJ6_34: J6.34 R222.1
NetJ6_38: J6.38 R223.1
NetJ6_40: J6.40 R224.1
NetJ6_44: J6.44 R225.1
NetJ6_46: J6.46 R226.1
NetJ6_50: J6.50 R227.1
NetJ6_51: J6.51 R59.2
NetJ6_52: J6.52 R228.1
NetJ6_53: J6.53 R60.2
NetJ6_55: J6.55 R61.2
NetJ6_56: J6.56 R229.1
NetJ6_57: J6.57 R62.2
NetJ6_58: J6.58 R230.1
NetJ6_59: J6.59 R63.2
NetQ1_1: Q1.1(G) R171.1
NetQ4_1: Q4.1(G) R66.1
NetR213_1: R213.1 S3.3 S3.4
NetR214_1: R214.1 R215.1 S3.1 S3.2

Not connected (* = marked no-connect by the designer): J6 14* 15* 16* 17* 19* 20* 21* 22* 23* 25* 27* 29* 31* 33* 35* 37* 39* 41* 43* 45* 47* 49*

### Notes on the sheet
- nERROR LED
- RESET LED
- USER LED
- RESET,  USER SWITCHES

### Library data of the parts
C52 = CMP-0006356-2: CAP, CERM, 0.1 uF, 50 V, +/- 10%, X7R, AEC-Q200 Grade 1, 0402; Manufacturer: MuRata; AEC Qualified: Y; SizeZ_mm: 0.6; VDC_V: 50V; AEC Category: Q200; AEC Grade: 1; Polarized: N; SizeArea_mm2: 0.5; SizeAreaWB_mm2: 3; TaMax_C: 125°C; TaMin_C: -55°C; U/M: EA; Value1: Unknown; Value: 0.1uF
C53 = CMP-0006356-2: as C123 on sheet PROC177B_CAN_LIN_PHY_Interface
C92 = CMP-0064967-2: CAP, CERM, 0.47 uF, 10 V,+/- 10%, X7S, 0402; Manufacturer: MuRata; Polarized: N; Value: 0.47uF; U/M: EA; Cap_F: 470nF; Value1: Unknown; VDC_V: 10V; TaMin_C: -55°C; TaMax_C: 125°C; Cap_Case: 0402; SizeArea_mm2: 0.5; SizeAreaWB_mm2: 3; SizeX_mm: 1; SizeZ_mm: 0.6; AEC Category: Q200
C93 = CMP-0006272-2: CAP, CERM, 1 uF, 10 V, +/- 10%, X6S, 0402; Manufacturer: TDK; Polarized: N; Value: 1uF; U/M: EA; Cap_F: 1µF; Value1: Unknown; VDC_V: 16V; TempCo: X5R; TaMin_C: -55°C; TaMax_C: 85°C; Cap_Case: 0402; SizeArea_mm2: 0.5; SizeAreaWB_mm2: 3; SizeX_mm: 1; SizeZ_mm: 0.6; AEC Category: Q200
C96 = CMP-0007497-5: CAP, CERM, 10 uF, 10 V, +/- 10%, X5R, 0603; Manufacturer: MuRata; Polarized: N; Value: 10uF; U/M: EA; Cap_F: 10µF; Tolerance_%: 20%; Value1: Unknown; VDC_V: 10V; TempCo: X7R; TaMin_C: -55°C; TaMax_C: 125°C; Cap_Case: 0603; SizeArea_mm2: 1.28; SizeAreaWB_mm2: 4.68; SizeX_mm: 1.6; SizeY_mm: 0.8; SizeZ_mm: 1; AEC Category: Q200
D5 D7 = CMP-0067682-2: LED, Green, SMD; Manufacturer: Kingbright; Angle: 120.0; Power_TotalModule: 75mW; SizeZ_mm: 0.6; Vf_V: 2.1V; Vr_V: 5V; Io_A: 20mA; Ir_A: 10µA; SizeArea_mm2: 0.5; SizeAreaWB_mm2: 3.0; SizeX_mm: 1.0; Tjmax_C: 85°C; Value1: 0.075W
D9 = CMP-0067681-2: LED, Red, SMD; Manufacturer: Kingbright; Vf_V: 1.95V; SizeAreaWB_mm2: 3.0; Tjmax_C: 85°C; SizeX_mm: 1.0; Io_A: 20mA; SizeArea_mm2: 0.5; Vr_V: 5V; Value1: 0.075W; SizeZ_mm: 0.6; Angle: 120.0; Ir_A: 10µA; Power_TotalModule: 75mW
J6 = CMP-0075524-1: Receptacle, 0.5 mm, 30x2, Gold, TH; Manufacturer: Samtec; Pitch_mm: 0.5; Gender: Female; Green_REACh: Passed; CT: False; Shrouded: N; RowSpacing_mm: 5.73; Green_Lifecycle: Active; Row_Count: 2
Q1 Q4 = CMP-0091833-1: N-Channel 20V 250mA (Ta) 500mW (Ta) Surface Mount VESM; Manufacturer: Toshiba; Threshold Vgs Min: 0.35V; QgTyp_nC: 0.34nC @ 4.5V; AEC Qualified: No; Rdson45_ohm: 0.75; TJmax_C: +150°C; Input Capacitace At Vds: 18pF @ 10V; SizeZ_mm: 0.55mm; Pulse Drain Current: 600mA; Threshold Vgs Max: 1V; Vgs_V: 10V; Typ Forward Diode Voltage: 0.8V; VdsMax_V: 1.2V; Power_W: 150mW; Number Of N Channels: 1; Turn Off Delay Time: 6.5ns; ChMode: False; Turn On Delay Time: 2ns
R28 R66 R141 R171 = CMP-0078212-1: as R252 on sheet PROC177B_FTDI
R30 = CMP-0025884-3: as R31 on sheet PROC177B_CAN_LIN_PHY_Interface
R34 R37-R42 R52 R53 R58-R63 R219-R230 = CMP-0002710-1: as R3 on sheet PROC177B_CAN_LIN_PHY_Interface
R64 R213 = CMP-0026878-3: RES, 220, 5%, 0.063 W, AEC-Q200 Grade 0, 0402; Manufacturer: Vishay-Dale; Power_W: 63mW; TempCo: 200 ppm/C; Value_Code: 220R; Value: 220; EIA_Code: E24; SizeX_mm: 1; SizeY_mm: 0.5; SizeZ_mm: 0.6; Value2: 0.063W; AEC Qualified: Y; VDC_V: 50V; AEC Category: Q200; AEC Grade: 0
R65 R123 R138 R165 = CMP-0025958-3: as R17 on sheet PROC177B_CAN_LIN_PHY_Interface
R214 = CMP-0002710-1: 0 Ohms Jumper Chip Resistor 0402 (1005 Metric) Automotive AEC-Q200 Thick Film; Manufacturer: Panasonic; AEC Qualified: Yes; SizeZ_mm: 0.4mm; AEC Grade: Grade 0; Power: 100mW; Value: 0
R215 = CMP-0025950-3: RES, 100 k, 1%, 0.063 W, AEC-Q200 Grade 0, 0402; Manufacturer: Vishay-Dale; AEC Category: Q200; AEC Grade: 0; AEC Qualified: Y; EIA_Code: E96; Power_W: 63mW; SizeArea_mm2: 0.5; SizeX_mm: 1; SizeZ_mm: 0.6; TempCo: 100 ppm/C; Value2: 0.063W; VDC_V: 50V
S2 = CMP-0079642-1: Switch, SPST-NO, Off-Mom, 0.05 A, 12 VDC, SMD; Manufacturer: C&K Components; SizeAreaWB_mm2: 88; SizeArea_mm2: 54; SizeZ_mm: 4.4; SizeY_mm: 6; VDC_V: 12V; CurrentRating_mA: 50A; PositionCount: 1; SizeX_mm: 9
S3 = CMP-0002325-1: Switch, SPST-NO, Off-Mom, 0.01 A, 32 VDC, SMD; Manufacturer: C&K Components; CurrentRating_mA: 10A; PositionCount: 1; SizeX_mm: 4.6; SizeY_mm: 2.8; SizeZ_mm: 1.9; SizeArea_mm2: 12.88; VDC_V: 32V; SizeAreaWB_mm2: 21.28
U17 = CMP-0051215-4: Single 3-Input Positive-AND Gate, DSF0006A, LARGE T&R; Manufacturer: Texas Instruments; Output Type: CMOS; Bits(#): 1; Input Type: CMOS/TTL; Technology Family: LVC; Schmitt Trigger: No; VCC(Max)(V): 5.5; Gate Type: AND; Rating: Catalog; Output Drive (IOL/IOH)(Max)(mA): 32/-32; ICC @ Nom Voltage(Max)(mA): 0.01; VCC(Min)(V): 1.65; F @ Nom Voltage(Max)(Mhz): 150; Logic: True; Voltage(Nom)(V): 1.8,2.5,3.3,5; tpd @ Nom Voltage(Max)(ns): 20,7.8,6.2,4.6

## Sheet PROC177B_I2C_SPI_Connector.SchDoc: I2C_SPI_INTERFACE_CONN_HEADER
size 431 x 279 mm; Date: Not shown in title block; ApprovedBy: Not shown in title block; CheckedBy: Not shown in title block; Author: Not shown in title block; CompanyName: Not shown in title block; DrawnBy: Mistral; Engineer: Not shown in title block; Organization: Not shown in title block; Address1: Not shown in title block; Address2: Not shown in title block; Address3: Not shown in title block; Address4: Not shown in title block; DocumentNumber: 16; Revision: Use project parameter SCH_Rev; SheetNumber: 16; SheetTotal: 17; PageSetup: Record=PageOptions¦CenterHorizontal=True¦CenterVertical=True¦PrintScale=1.00¦XCorrection=1.00¦YCorrection=1.00¦PrintKind=0¦BorderSize=5000000¦LeftOffset=0¦BottomOffset=0¦Orientation=2¦PaperLength=1000¦PaperWidth=1000¦Scale=100¦PaperSource=15¦PrintQuality=600¦MediaType=1¦DitherType=10¦PaperKind=Letter¦PrintScaleMode=1
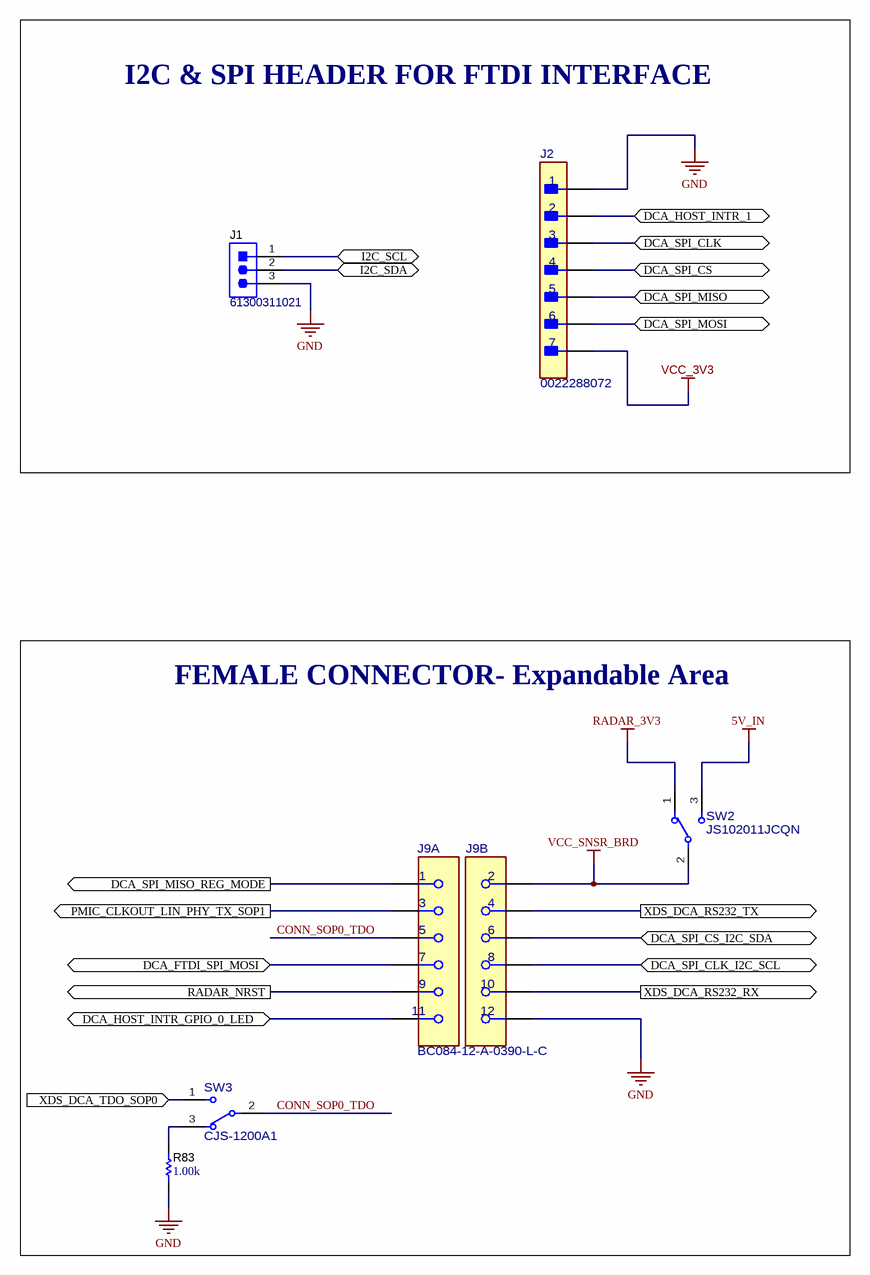
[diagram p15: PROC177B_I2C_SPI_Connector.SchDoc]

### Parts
J1  61300311021  [Wurth_61300311021]
J2  0022288072  [FP-0022288072_HDR7-MFG]
J9  BC084-12-A-0390-L-C  [FP-BC084-12-A-0390-L-C_CONN_RCPT12-MFG]  (parts A,B of 2)
R83  ValueDisplayed: 1.00k  [0402]  (hidden comment: CRCW04021K00FKED)
SW2  JS102011JCQN  [FP-JS102011JCQN_SMD3-MFG]
SW3  CJS-1200A1  [FP-CJS-1200A1_SMT3-MFG]

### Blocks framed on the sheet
I2C & SPI HEADER FOR FTDI INTERFACE: J1 J2
FEMALE CONNECTOR- Expandable Area: J9 R83 SW2 SW3

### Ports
DCA_FTDI_SPI_MOSI (bidir), DCA_HOST_INTR_1 (bidir), DCA_HOST_INTR_GPIO_0_LED (bidir), DCA_SPI_CLK (bidir), DCA_SPI_CLK_I2C_SCL (bidir), DCA_SPI_CS (bidir), DCA_SPI_CS_I2C_SDA (bidir), DCA_SPI_MISO (bidir), DCA_SPI_MISO_REG_MODE (out), DCA_SPI_MOSI (bidir), I2C_SCL (bidir), I2C_SDA (bidir), PMIC_CLKOUT_LIN_PHY_TX_SOP1 (out), RADAR_NRST (out), XDS_DCA_RS232_RX (out), XDS_DCA_RS232_TX (out), XDS_DCA_TDO_SOP0 (in)

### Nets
5V_IN: SW2.3
GND: J1.3 J2.1 J9.12 R83.1
RADAR_3V3: SW2.1
VCC_3V3: J2.7
VCC_SNSR_BRD: J9.2 SW2.2
CONN_SOP0_TDO: J9.5 SW3.2(C)
DCA_FTDI_SPI_MOSI: J9.7 ; port DCA_FTDI_SPI_MOSI
DCA_HOST_INTR_1: J2.2 ; port DCA_HOST_INTR_1
DCA_HOST_INTR_GPIO_0_LED: J9.11 ; port DCA_HOST_INTR_GPIO_0_LED
DCA_SPI_CLK: J2.3 ; port DCA_SPI_CLK
DCA_SPI_CLK_I2C_SCL: J9.8 ; port DCA_SPI_CLK_I2C_SCL
DCA_SPI_CS: J2.4 ; port DCA_SPI_CS
DCA_SPI_CS_I2C_SDA: J9.6 ; port DCA_SPI_CS_I2C_SDA
DCA_SPI_MISO: J2.5 ; port DCA_SPI_MISO
DCA_SPI_MISO_REG_MODE: J9.1 ; port DCA_SPI_MISO_REG_MODE
DCA_SPI_MOSI: J2.6 ; port DCA_SPI_MOSI
I2C_SCL: J1.1 ; port I2C_SCL
I2C_SDA: J1.2 ; port I2C_SDA
PMIC_CLKOUT_LIN_PHY_TX_SOP1: J9.3 ; port PMIC_CLKOUT_LIN_PHY_TX_SOP1
RADAR_NRST: J9.9 ; port RADAR_NRST
XDS_DCA_RS232_RX: J9.10 ; port XDS_DCA_RS232_RX
XDS_DCA_RS232_TX: J9.4 ; port XDS_DCA_RS232_TX
XDS_DCA_TDO_SOP0: SW3.1 ; port XDS_DCA_TDO_SOP0
NetR83_2: R83.2 SW3.3

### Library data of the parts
J1 = CMP-0054795-1: Header, 2.54 mm, 3x1, Gold, R/A, TH; Manufacturer: Wurth Elektronik; CNHeader: TRUE; Shrouded: N; Gender: Male; Row_Count: 1; Pitch_mm: 2.54; CT: FALSE
J2 = CMP-0120118-1: Manufacturer: Molex; ContactFinish: Gold,Nickel; Current_A: 4A; Row_Count: 1; Voltage_V: 600V; AEC Qualified: No; Conn Gender: Male; Conn Orientation: Right Angle; DUT-Pitch_mm: 2.54mm; SizeZ_mm: 2.74mm
J9 = CMP-0049930-1: Manufacturer: GCT; ContactFinish: Gold,Nickel; Current_A: 1A; Row_Count: 2; Voltage_V: 250V; AEC Qualified: No; Conn Gender: Female; Conn Orientation: Straight; DUT-Pitch_mm: 1mm; Is Female: yes; SizeZ_mm: 2.45mm
R83 = CMP-0026071-3: as R21 on sheet PROC177B_CAN_LIN_PHY_Interface
SW2 = CMP-0120644-1: C & K COMPONENTS - - Schiebeschalter, Subminiatur, SPDT, Ein-Ein, Oberflächenmontage, JS Series, 300 mA; SizeZ_mm: 5.6mm; VDC_V: 6V; AEC Qualified: No; Coil Resistance_ohm: 70mΩ; Contact Current Rating: 0.3A; Electromechanical Life: 5000Cycles
SW3 = CMP-0120641-1: Slide Switch SPDT Surface Mount; Manufacturer: Nidec Components Corporation; PositionCount: 1; SizeZ_mm: 2.5mm; VDC_V: 6V; AEC Qualified: No; Coil Resistance_ohm: 100mΩ; Contact Current Rating: 100mA; Electromechanical Life: 200Cycles; Standoff Height: 0mm

## Sheet PROC177B_EVM_Hardware.SchDoc: HARDWARE
size 431 x 279 mm; Date: Not shown in title block; ApprovedBy: Not shown in title block; CheckedBy: Not shown in title block; Author: Not shown in title block; CompanyName: Not shown in title block; DrawnBy: Mistral; Engineer: Not shown in title block; Organization: Not shown in title block; Address1: Not shown in title block; Address2: Not shown in title block; Address3: Not shown in title block; Address4: Not shown in title block; DocumentNumber: 16; Revision: Use project parameter SCH_Rev; SheetNumber: 16; SheetTotal: 16; PageSetup: Record=PageOptions¦CenterHorizontal=True¦CenterVertical=True¦PrintScale=1.00¦XCorrection=1.00¦YCorrection=1.00¦PrintKind=0¦BorderSize=5000000¦LeftOffset=0¦BottomOffset=0¦Orientation=2¦PaperLength=1000¦PaperWidth=1000¦Scale=100¦PaperSource=15¦PrintQuality=600¦MediaType=1¦DitherType=10¦PaperKind=Letter¦PrintScaleMode=1
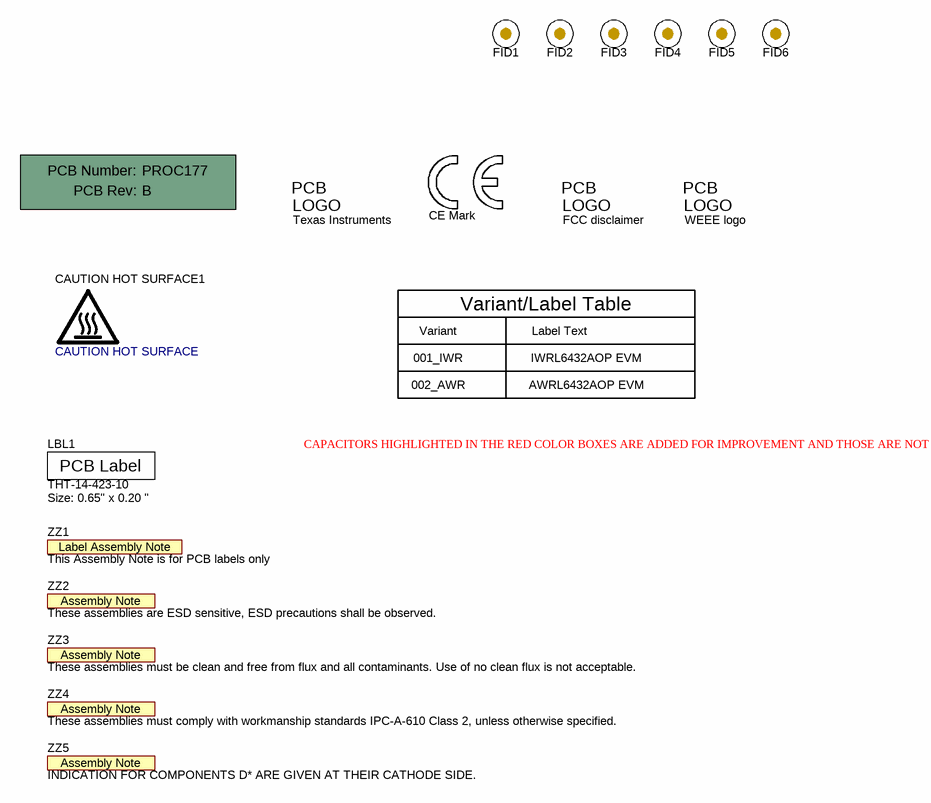
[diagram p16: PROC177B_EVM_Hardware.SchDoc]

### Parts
!PCB  Printed Circuit Board  (value not drawn)  (mechanical)
CAUTION_HOT_SURFACE1  CAUTION HOT SURFACE  [IEC_HotSurface_Small]  (no BOM)
FID1  Fiducial  [Fiducial10-20]  (value not drawn)
FID2  Fiducial  [Fiducial10-20]  (value not drawn)
FID3  Fiducial  [Fiducial10-20]  (value not drawn)
FID4  Fiducial  [Fiducial10-20]  (value not drawn)
FID5  Fiducial  [Fiducial10-20]  (value not drawn)
FID6  Fiducial  [Fiducial10-20]  (value not drawn)
LBL1  THT-14-423-10  Note: Size: 0.65" x 0.20 "  [Label_650x200]
Logo1  Texas Instruments  [TI_Stacked_Overlay_Small]  (no BOM)
Logo2  CE Mark  [CE_Mark_5mm]  (no BOM)
Logo3  FCC disclaimer  [FCC_disclaimer]  (no BOM)
Logo4  WEEE logo  [WEEE_Minimum]  (no BOM)
ZZ1  This Assembly Note is for PCB labels only  [AssemblyNoteLabel]  (no BOM)
ZZ2  These assemblies are ESD sensitive, ESD precautions shall be observed.  [AssemblyNote]  (no BOM)
ZZ3  These assemblies must be clean and free from flux and all contaminants. Use of no clean flux is not acceptable.  [AssemblyNote]  (no BOM)
ZZ4  These assemblies must comply with workmanship standards IPC-A-610 Class 2, unless otherwise specified.  [AssemblyNote]  (no BOM)
ZZ5  INDICATION FOR COMPONENTS D* ARE GIVEN AT THEIR CATHODE SIDE.  [AssemblyNote]  (no BOM)

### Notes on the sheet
- Variant
- 001_IWR
- Variant/Label Table
- Label Text
- IWRL6432AOP EVM
- 002_AWR
- AWRL6432AOP EVM
- CAPACITORS HIGHLIGHTED IN THE RED COLOR BOXES ARE ADDED FOR IMPROVEMENT AND THOSE ARE NOT MANDITORY.

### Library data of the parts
!PCB = CMP-0003618-2: Manufacturer: Any; PartNumber: PROC177
CAUTION_HOT_SURFACE1 = CMP-0074837-2: IEC 61010-1 Hot Surface Warning; Manufacturer: Texas Instruments; SymbolCreator: a0412235; AEC Category: Q200; CompType: IC
FID1-FID6 = CMP-0077181-1: Fiducial mark.  There is nothing to buy or mount.
LBL1 = CMP-0003625-1: Thermal Transfer Printable Labels, 0.650" W x 0.200" H - 10,000 per roll; Manufacturer: Brady; CompType: Label
Logo1 = CMP-0074838-1: Texas Instrument Corporate Signature; SymbolCreator: a0412235; Lib Reference: TI_Logo; Library Reference: Logo
Logo2 = CMP-0074844-1: SymbolCreator: a0412235
Logo3 = CMP-0074847-1: FCC_disclaimer; Library Reference: Logo
Logo4 = CMP-0074769-1
ZZ1 = CMP-0003616-3
ZZ2 = CMP-0077236-1
ZZ3 = CMP-0077237-1
ZZ4 ZZ5 = CMP-0077238-1

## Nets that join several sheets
5V_IN: PROC177B_USB_PWR_DC_Jack_Switch (7 pins), PROC177B_DC_Regulators (14 pins), PROC177B_XDS110_Interface (C42.1 U13.6), PROC177B_CAN_LIN_PHY_Interface (J4.1 R31.1 R69.2), PROC177B_DCA1000_Connector_Reset (R30.1 R141.2), PROC177B_I2C_SPI_Connector (SW2.3)
FTDI_VBUS: PROC177B_USB_PWR_DC_Jack_Switch (L8.1), PROC177B_FTDI (C157.1 J10.1 R259.2)
GND: PROC177B_USB_PWR_DC_Jack_Switch (31 pins), PROC177B_DC_Regulators (31 pins), PROC177B_xWRL6432AoP_Chip (43 pins), PROC177B_Decoupling_caps_QSPI_Flash_ (34 pins), PROC177B_Temp_Current_sensors_EPROM (23 pins), PROC177B_LVDS_Driver (12 pins), PROC177B_Analog_Mux_SOP_Ctrl (19 pins), PROC177B_Analog_MUX_SPI (C56.2 R10.2 U28.3 U28.5), PROC177B_XDS110_Interface (38 pins), PROC177B_CAN_LIN_PHY_Interface (10 pins), PROC177B_FTDI (37 pins), PROC177B_DCA1000_Connector_Reset (24 pins), PROC177B_I2C_SPI_Connector (J1.3 J2.1 J9.12 R83.1)
RADAR_1P2_RF: PROC177B_xWRL6432AoP_Chip (5 pins), PROC177B_Decoupling_caps_QSPI_Flash_ (C20.2 C24.2 C44.1 C101.2), PROC177B_Temp_Current_sensors_EPROM (R134.2 U25.9)
RADAR_1V2: PROC177B_xWRL6432AoP_Chip (R77.2 R86.2 TP15.1 U1.K2), PROC177B_Decoupling_caps_QSPI_Flash_ (5 pins), PROC177B_Temp_Current_sensors_EPROM (R193.2 U8.9)
RADAR_1V4_APLL: PROC177B_xWRL6432AoP_Chip (U1.G8), PROC177B_Decoupling_caps_QSPI_Flash_ (C22.2)
RADAR_1V4_SYNTH: PROC177B_xWRL6432AoP_Chip (U1.F7), PROC177B_Decoupling_caps_QSPI_Flash_ (C18.2)
RADAR_1V8: PROC177B_xWRL6432AoP_Chip (17 pins), PROC177B_Decoupling_caps_QSPI_Flash_ (10 pins), PROC177B_Temp_Current_sensors_EPROM (R192.2 U6.9)
RADAR_1V_RF_OUT: PROC177B_xWRL6432AoP_Chip (5 pins), PROC177B_Decoupling_caps_QSPI_Flash_ (C9.2 C19.2 C23.1)
RADAR_3V3: PROC177B_xWRL6432AoP_Chip (9 pins), PROC177B_Decoupling_caps_QSPI_Flash_ (9 pins), PROC177B_Temp_Current_sensors_EPROM (R200.2 U7.9), PROC177B_I2C_SPI_Connector (SW2.1)
RADAR_SRAM_1V2: PROC177B_xWRL6432AoP_Chip (R77.1 U1.M1 U1.M2 U1.N2), PROC177B_Decoupling_caps_QSPI_Flash_ (C25.2 C26.2)
RADAR_VBGAP: PROC177B_xWRL6432AoP_Chip (U1.H10), PROC177B_Decoupling_caps_QSPI_Flash_ (C6.1)
REG_1V2: PROC177B_DC_Regulators (C61.2 L5.2), PROC177B_Temp_Current_sensors_EPROM (R193.1 U8.8 U8.10)
REG_1V8: PROC177B_DC_Regulators (C68.2 L6.2 R9.1), PROC177B_Temp_Current_sensors_EPROM (R192.1 U6.8 U6.10)
REG_RF_1V2: PROC177B_DC_Regulators (C79.2 L1.2), PROC177B_Temp_Current_sensors_EPROM (R134.1 U25.8 U25.10)
VCC_3V3: PROC177B_USB_PWR_DC_Jack_Switch (R172.2), PROC177B_DC_Regulators (5 pins), PROC177B_Temp_Current_sensors_EPROM (32 pins), PROC177B_LVDS_Driver (C91.1 R90.1 R129.1 U15.8), PROC177B_Analog_Mux_SOP_Ctrl (14 pins), PROC177B_Analog_MUX_SPI (C56.1 R12.1 U28.8), PROC177B_CAN_LIN_PHY_Interface (C38.2 R17.2 R22.2 U5.5), PROC177B_FTDI (R99.2), PROC177B_DCA1000_Connector_Reset (9 pins), PROC177B_I2C_SPI_Connector (J2.7)
VCC_XDS_3V3: PROC177B_XDS110_Interface (30 pins), PROC177B_FTDI (L7.1)
XDSET_1_VBUS: PROC177B_USB_PWR_DC_Jack_Switch (R1.1 U9.6), PROC177B_XDS110_Interface (R169.2 R236.2)
CAN_PHY_RX: PROC177B_Analog_Mux_SOP_Ctrl (U12.5), PROC177B_CAN_LIN_PHY_Interface (R80.1)
CAN_PHY_TX: PROC177B_Analog_Mux_SOP_Ctrl (U12.9), PROC177B_CAN_LIN_PHY_Interface (R78.1)
CAN_STB_CTRL: PROC177B_Analog_Mux_SOP_Ctrl (S4.1), PROC177B_CAN_LIN_PHY_Interface (R3.1)
DCA_FTDI_HOST_INTR_1: PROC177B_Analog_Mux_SOP_Ctrl (R23.2 R152.1 U24.12), PROC177B_Analog_MUX_SPI (U28.10)
DCA_FTDI_SPI_CLK: PROC177B_Analog_Mux_SOP_Ctrl (U24.16), PROC177B_Analog_MUX_SPI (U28.4)
DCA_FTDI_SPI_CS: PROC177B_Analog_Mux_SOP_Ctrl (U24.3), PROC177B_Analog_MUX_SPI (U28.6)
DCA_FTDI_SPI_MISO: PROC177B_Analog_Mux_SOP_Ctrl (U24.9), PROC177B_Analog_MUX_SPI (U28.7)
DCA_FTDI_SPI_MOSI: PROC177B_xWRL6432AoP_Chip (J8.8 U1.E3), PROC177B_Analog_MUX_SPI (U28.9), PROC177B_I2C_SPI_Connector (J9.7)
DCA_HOST_INTR_1: PROC177B_Analog_MUX_SPI (U28.19), PROC177B_DCA1000_Connector_Reset (R42.2), PROC177B_I2C_SPI_Connector (J2.2)
DCA_HOST_INTR_GPIO_0_LED: PROC177B_xWRL6432AoP_Chip (J8.12 U1.J2), PROC177B_Analog_Mux_SOP_Ctrl (U24.10), PROC177B_I2C_SPI_Connector (J9.11)
DCA_RS232_RX: PROC177B_Analog_Mux_SOP_Ctrl (U12.3), PROC177B_DCA1000_Connector_Reset (R61.1)
DCA_RS232_TX: PROC177B_Analog_Mux_SOP_Ctrl (U12.15), PROC177B_DCA1000_Connector_Reset (R62.1)
DCA_SPI_CLK: PROC177B_Analog_MUX_SPI (U28.2), PROC177B_DCA1000_Connector_Reset (R41.1), PROC177B_I2C_SPI_Connector (J2.3)
DCA_SPI_CLK_I2C_SCL: PROC177B_xWRL6432AoP_Chip (J8.7 R75.1 U1.F1), PROC177B_Analog_Mux_SOP_Ctrl (U24.2), PROC177B_I2C_SPI_Connector (J9.8)
DCA_SPI_CS: PROC177B_Analog_MUX_SPI (U28.1), PROC177B_DCA1000_Connector_Reset (R39.1), PROC177B_I2C_SPI_Connector (J2.4)
DCA_SPI_CS_I2C_SDA: PROC177B_xWRL6432AoP_Chip (J8.5 R4.1 U1.F4), PROC177B_Analog_Mux_SOP_Ctrl (U24.5), PROC177B_I2C_SPI_Connector (J9.6)
DCA_SPI_MISO: PROC177B_Analog_MUX_SPI (U28.23), PROC177B_DCA1000_Connector_Reset (R53.2), PROC177B_I2C_SPI_Connector (J2.5)
DCA_SPI_MISO_REG_MODE: PROC177B_xWRL6432AoP_Chip (J8.2 U1.E4), PROC177B_Analog_Mux_SOP_Ctrl (U24.7), PROC177B_I2C_SPI_Connector (J9.1)
DCA_SPI_MOSI: PROC177B_Analog_MUX_SPI (U28.21), PROC177B_DCA1000_Connector_Reset (R52.1), PROC177B_I2C_SPI_Connector (J2.6)
DCA_TCK: PROC177B_Analog_Mux_SOP_Ctrl (U4.16), PROC177B_DCA1000_Connector_Reset (R38.2)
DCA_TDI: PROC177B_Analog_Mux_SOP_Ctrl (U4.3), PROC177B_DCA1000_Connector_Reset (R37.1)
DCA_TDO: PROC177B_Analog_Mux_SOP_Ctrl (U4.9), PROC177B_DCA1000_Connector_Reset (R34.2)
DCA_TMS: PROC177B_Analog_Mux_SOP_Ctrl (U4.12), PROC177B_DCA1000_Connector_Reset (R40.2)
FTDI_HOST_INTR_1: PROC177B_Analog_MUX_SPI (U28.18), PROC177B_FTDI (R216.2 R217.2)
FTDI_SOP0: PROC177B_Analog_Mux_SOP_Ctrl (R13.1 R43.2), PROC177B_FTDI (R249.2)
FTDI_SOP1: PROC177B_Analog_Mux_SOP_Ctrl (R16.1 R67.2), PROC177B_FTDI (R248.2)
FTDI_SPI_CLK: PROC177B_Analog_MUX_SPI (U28.11), PROC177B_FTDI (R186.2)
FTDI_SPI_CS: PROC177B_Analog_MUX_SPI (U28.13), PROC177B_FTDI (R99.1 R209.2)
FTDI_SPI_MISO: PROC177B_Analog_MUX_SPI (U28.15), PROC177B_FTDI (R189.2)
FTDI_SPI_MOSI: PROC177B_Analog_MUX_SPI (U28.17), PROC177B_FTDI (R187.2)
I2C_SCL: PROC177B_Temp_Current_sensors_EPROM (7 pins), PROC177B_Analog_Mux_SOP_Ctrl (U24.1), PROC177B_XDS110_Interface (R199.1 S5.2), PROC177B_DCA1000_Connector_Reset (R60.1), PROC177B_I2C_SPI_Connector (J1.1)
I2C_SDA: PROC177B_Temp_Current_sensors_EPROM (7 pins), PROC177B_Analog_Mux_SOP_Ctrl (U24.4), PROC177B_XDS110_Interface (R197.1 S5.1), PROC177B_DCA1000_Connector_Reset (R59.1), PROC177B_I2C_SPI_Connector (J1.2)
LIN_PHY_EN_CTRL: PROC177B_Analog_Mux_SOP_Ctrl (S4.2), PROC177B_CAN_LIN_PHY_Interface (R88.1)
LIN_PHY_RX: PROC177B_LVDS_Driver (U15.22), PROC177B_CAN_LIN_PHY_Interface (R18.1 R22.1)
LVDS_CLK_RTC_CLKIN_TP: PROC177B_xWRL6432AoP_Chip (U1.L4), PROC177B_LVDS_Driver (U15.10)
LVDS_D0_LIN_PHY_RX: PROC177B_xWRL6432AoP_Chip (U1.H2), PROC177B_LVDS_Driver (U15.12)
LVDS_D1_XDS_UARTA_RX_CAN_RX: PROC177B_xWRL6432AoP_Chip (U1.J3), PROC177B_LVDS_Driver (U15.6)
LVDS_D2_XDS_UARTA_TX_CAN_TX: PROC177B_xWRL6432AoP_Chip (U1.K3), PROC177B_LVDS_Driver (U15.7)
LVDS_D3_nERROR_LED_WD_TP: PROC177B_xWRL6432AoP_Chip (U1.J4), PROC177B_LVDS_Driver (U15.4)
LVDS_FRCLK_HOST_CLK_TP: PROC177B_xWRL6432AoP_Chip (U1.L3), PROC177B_LVDS_Driver (U15.9)
MUX_CTRL_FTDI_DCA_SPI: PROC177B_Analog_Mux_SOP_Ctrl (S4.3), PROC177B_Analog_MUX_SPI (R12.2 U28.14 U28.24)
MUX_CTRL_LVDS_UART_CAN_TP: PROC177B_LVDS_Driver (R90.2 U15.14 U15.24), PROC177B_Analog_Mux_SOP_Ctrl (S1.3)
nERROR_LED_WD_TP: PROC177B_LVDS_Driver (TP2.1 U15.2), PROC177B_DCA1000_Connector_Reset (D9.2 R65.2)
PGOOD: PROC177B_USB_PWR_DC_Jack_Switch (R179.1), PROC177B_DC_Regulators (R198.1 R201.2), PROC177B_XDS110_Interface (R241.1), PROC177B_DCA1000_Connector_Reset (R58.1)
PMIC_CLKOUT_LIN_PHY_TX_SOP1: PROC177B_xWRL6432AoP_Chip (J8.4 TP13.1 U1.H3), PROC177B_Analog_Mux_SOP_Ctrl (R15.1 R206.1), PROC177B_CAN_LIN_PHY_Interface (R19.1), PROC177B_I2C_SPI_Connector (J9.3)
QSPI_CS: PROC177B_xWRL6432AoP_Chip (U1.D3), PROC177B_Decoupling_caps_QSPI_Flash_ (R50.2 U2.1)
QSPI_D0: PROC177B_xWRL6432AoP_Chip (U1.C2), PROC177B_Decoupling_caps_QSPI_Flash_ (R45.2)
QSPI_D1: PROC177B_xWRL6432AoP_Chip (U1.C3), PROC177B_Decoupling_caps_QSPI_Flash_ (R46.1)
QSPI_D2: PROC177B_xWRL6432AoP_Chip (U1.C4), PROC177B_Decoupling_caps_QSPI_Flash_ (R44.1 R47.1)
QSPI_D3: PROC177B_xWRL6432AoP_Chip (U1.B3 U1.B4), PROC177B_Decoupling_caps_QSPI_Flash_ (R49.1 R51.2)
QSPI_SCLK: PROC177B_xWRL6432AoP_Chip (U1.D2), PROC177B_Decoupling_caps_QSPI_Flash_ (R48.2)
RADAR_LVDS_0M: PROC177B_LVDS_Driver (U10.3), PROC177B_DCA1000_Connector_Reset (R230.2)
RADAR_LVDS_0P: PROC177B_LVDS_Driver (U10.2), PROC177B_DCA1000_Connector_Reset (R229.2)
RADAR_LVDS_1M: PROC177B_LVDS_Driver (U10.13), PROC177B_DCA1000_Connector_Reset (R228.2)
RADAR_LVDS_1P: PROC177B_LVDS_Driver (U10.14), PROC177B_DCA1000_Connector_Reset (R227.2)
RADAR_LVDS_2M: PROC177B_LVDS_Driver (U10.11), PROC177B_DCA1000_Connector_Reset (R224.2)
RADAR_LVDS_2P: PROC177B_LVDS_Driver (U10.10), PROC177B_DCA1000_Connector_Reset (R223.2)
RADAR_LVDS_3M: PROC177B_LVDS_Driver (U10.5), PROC177B_DCA1000_Connector_Reset (R222.2)
RADAR_LVDS_3P: PROC177B_LVDS_Driver (U10.6), PROC177B_DCA1000_Connector_Reset (R221.2)
RADAR_LVDS_CLKM: PROC177B_LVDS_Driver (U14.3), PROC177B_DCA1000_Connector_Reset (R226.2)
RADAR_LVDS_CLKP: PROC177B_LVDS_Driver (U14.2), PROC177B_DCA1000_Connector_Reset (R225.2)
RADAR_LVDS_FRCLKM: PROC177B_LVDS_Driver (U14.5), PROC177B_DCA1000_Connector_Reset (R220.2)
RADAR_LVDS_FRCLKP: PROC177B_LVDS_Driver (U14.6), PROC177B_DCA1000_Connector_Reset (R219.2)
RADAR_NRST: PROC177B_DC_Regulators (R176.1), PROC177B_xWRL6432AoP_Chip (5 pins), PROC177B_DCA1000_Connector_Reset (R171.2 U17.4), PROC177B_I2C_SPI_Connector (J9.9)
RADAR_NRST_2: PROC177B_FTDI (R243.2), PROC177B_DCA1000_Connector_Reset (5 pins)
REG_MODE_SELECT: PROC177B_DC_Regulators (R173.2), PROC177B_Analog_Mux_SOP_Ctrl (U24.8)
USER_LED_SW_GPIO_0: PROC177B_Analog_Mux_SOP_Ctrl (U24.11), PROC177B_FTDI (R242.2), PROC177B_DCA1000_Connector_Reset (R66.2 R214.2)
XDS_DCA_RS232_RX: PROC177B_xWRL6432AoP_Chip (J8.9 R74.1 U1.G2), PROC177B_Analog_Mux_SOP_Ctrl (U12.2), PROC177B_I2C_SPI_Connector (J9.10)
XDS_DCA_RS232_TX: PROC177B_xWRL6432AoP_Chip (J8.3 R73.1 U1.H4), PROC177B_Analog_Mux_SOP_Ctrl (U12.14), PROC177B_I2C_SPI_Connector (J9.4)
XDS_DCA_TCK: PROC177B_xWRL6432AoP_Chip (U1.F3), PROC177B_Analog_Mux_SOP_Ctrl (U4.2)
XDS_DCA_TDI: PROC177B_xWRL6432AoP_Chip (U1.F2), PROC177B_Analog_Mux_SOP_Ctrl (U4.5)
XDS_DCA_TDO_SOP0: PROC177B_xWRL6432AoP_Chip (J8.6 R93.1), PROC177B_Analog_Mux_SOP_Ctrl (R203.1 U4.7), PROC177B_I2C_SPI_Connector (SW3.1)
XDS_DCA_TMS: PROC177B_xWRL6432AoP_Chip (U1.G3), PROC177B_Analog_Mux_SOP_Ctrl (U4.10)
XDS_NRST: PROC177B_XDS110_Interface (R126.2), PROC177B_DCA1000_Connector_Reset (R138.1 U17.3)
XDS_RS232_RX: PROC177B_Analog_Mux_SOP_Ctrl (U12.1), PROC177B_XDS110_Interface (R24.2 R188.1)
XDS_RS232_TX: PROC177B_Analog_Mux_SOP_Ctrl (U12.13), PROC177B_XDS110_Interface (R26.2 R181.1)
XDS_SOP0: PROC177B_Analog_Mux_SOP_Ctrl (R43.1), PROC177B_XDS110_Interface (U21.42)
XDS_SOP1: PROC177B_Analog_Mux_SOP_Ctrl (R67.1), PROC177B_XDS110_Interface (U21.43)
XDS_TCK: PROC177B_Analog_Mux_SOP_Ctrl (U4.1), PROC177B_XDS110_Interface (R122.2)
XDS_TDI: PROC177B_Analog_Mux_SOP_Ctrl (U4.4), PROC177B_XDS110_Interface (R125.2)
XDS_TDO: PROC177B_Analog_Mux_SOP_Ctrl (U4.8), PROC177B_XDS110_Interface (U21.37)
XDS_TMS: PROC177B_Analog_Mux_SOP_Ctrl (U4.11), PROC177B_XDS110_Interface (R124.2)
XDS_UARTA_RX: PROC177B_Analog_Mux_SOP_Ctrl (R127.2 U12.7), PROC177B_XDS110_Interface (R24.1 R82.1)
XDS_UARTA_RX_CAN_RX: PROC177B_LVDS_Driver (U15.1), PROC177B_Analog_Mux_SOP_Ctrl (R127.1 U12.6)
XDS_UARTA_TX: PROC177B_Analog_Mux_SOP_Ctrl (R128.2 U12.11), PROC177B_XDS110_Interface (R26.1 R81.1 R190.1)
XDS_UARTA_TX_CAN_TX: PROC177B_LVDS_Driver (U15.23), PROC177B_Analog_Mux_SOP_Ctrl (R128.1 U12.10)
XDSET_1_DM: PROC177B_USB_PWR_DC_Jack_Switch (J5.2 U9.4), PROC177B_XDS110_Interface (U21.93)
XDSET_1_DP: PROC177B_USB_PWR_DC_Jack_Switch (J5.3 U9.5), PROC177B_XDS110_Interface (U21.94)
XDSET_1_ID: PROC177B_USB_PWR_DC_Jack_Switch (J5.4 U9.2), PROC177B_XDS110_Interface (R170.2)

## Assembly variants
001_IWR: not fitted C1 C100 C121 C122 C130 C131 FB2 FID1 FID2 FID3 FID4 FID5 FID6 R2 R14 R15 R24 R26 R30 R32 R36 R57 R59 R60 R65 R107 R113 R114 R116 R121 R127 R128 R135 R150 R152 R157 R161 R176 R197 R199 R242 R248 R249
002_AWR: not fitted C1 C100 C121 C122 C130 C131 FB2 FID1 FID2 FID3 FID4 FID5 FID6 R2 R14 R15 R24 R26 R30 R32 R36 R57 R59 R60 R65 R107 R113 R114 R116 R121 R127 R128 R135 R150 R152 R157 R161 R176 R197 R199 R242 R248 R249; alternate parts U1 -> CMP-0120793-2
